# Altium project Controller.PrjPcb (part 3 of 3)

## Sheet Fault Logic - S.SchDoc: FAULT LOGIC (S) - 60KW GM4 DAB CONTROL
size 431 x 279 mm; Date: 02/2025; DocumentNumber: CRD60DD12N-GMB-CONTROL; Revision: 2.0; SheetNumber: 8; SheetTotal: 12; SheetSize: B
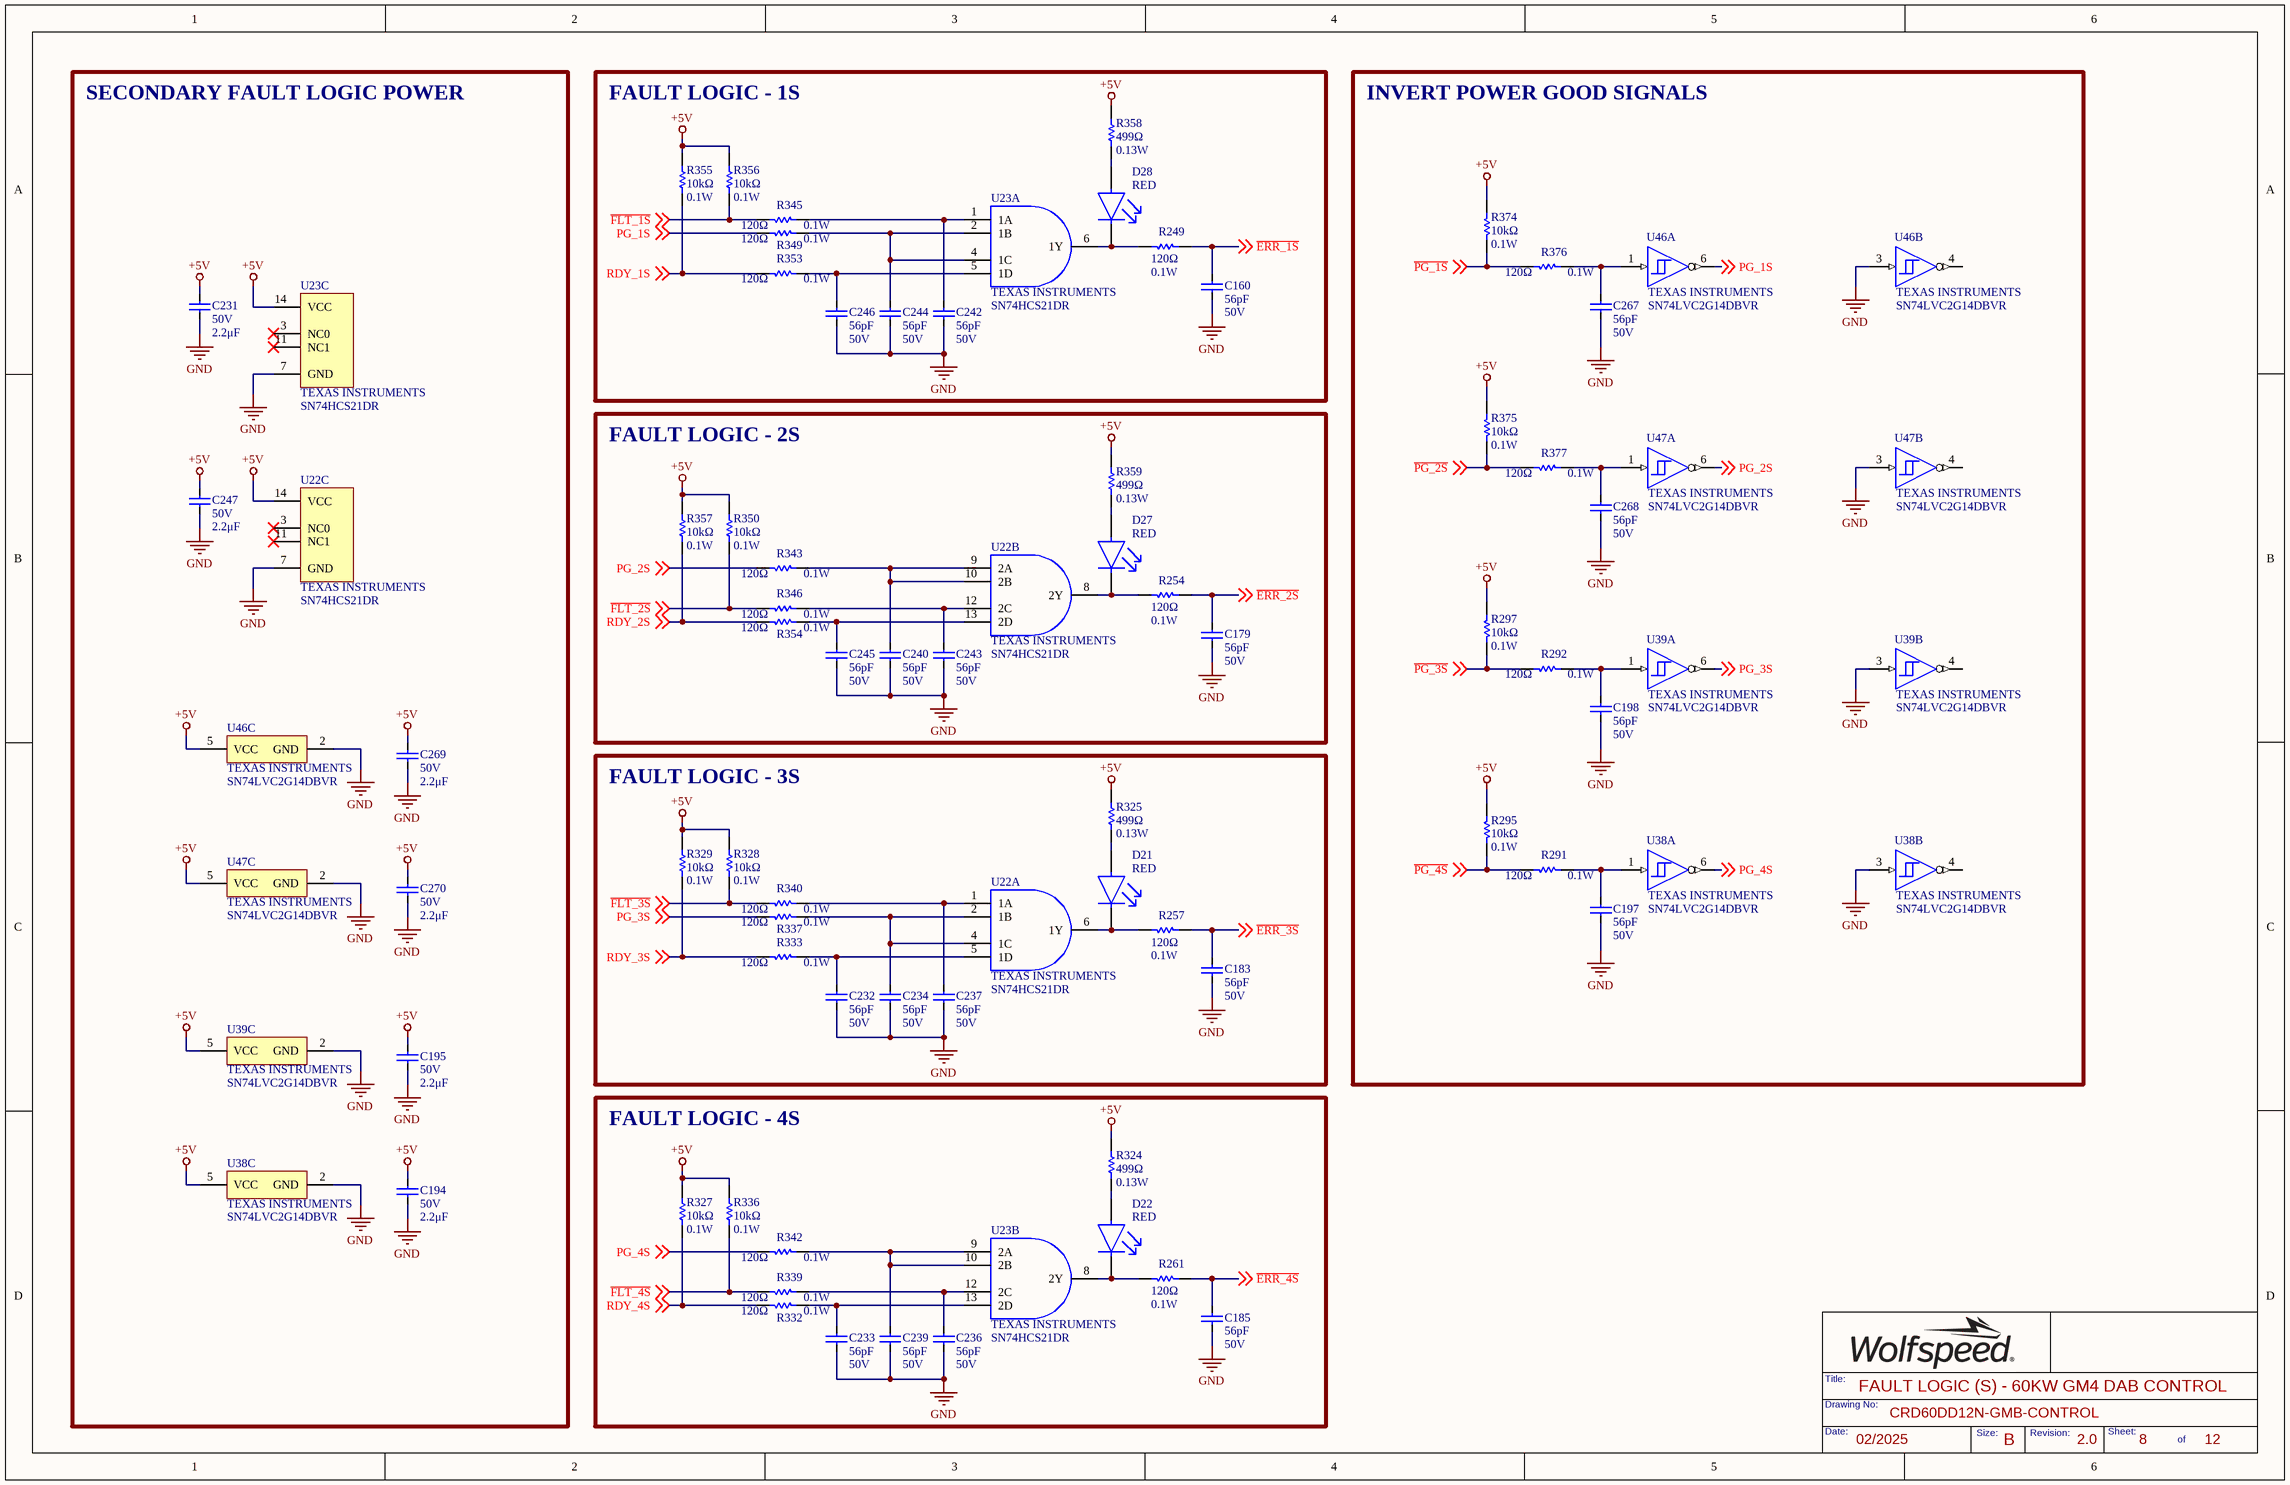
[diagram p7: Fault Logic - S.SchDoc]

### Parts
C160  Capacitance: 56pF  Voltage Rating: 50V  [FP-C0603C-CF-IPC_B]  (hidden comment: CL10C560JB8NNNC)
C179  Capacitance: 56pF  Voltage Rating: 50V  [FP-C0603C-CF-IPC_B]  (hidden comment: CL10C560JB8NNNC)
C183  Capacitance: 56pF  Voltage Rating: 50V  [FP-C0603C-CF-IPC_B]  (hidden comment: CL10C560JB8NNNC)
C185  Capacitance: 56pF  Voltage Rating: 50V  [FP-C0603C-CF-IPC_B]  (hidden comment: CL10C560JB8NNNC)
C194  Voltage Rating: 50V  Capacitance: 2.2μF  [FP-C0603C-CF-IPC_B]  (hidden comment: GRT188R61H225ME13D)
C195  Voltage Rating: 50V  Capacitance: 2.2μF  [FP-C0603C-CF-IPC_B]  (hidden comment: GRT188R61H225ME13D)
C197  Capacitance: 56pF  Voltage Rating: 50V  [FP-C0603C-CF-IPC_B]  (hidden comment: CL10C560JB8NNNC)
C198  Capacitance: 56pF  Voltage Rating: 50V  [FP-C0603C-CF-IPC_B]  (hidden comment: CL10C560JB8NNNC)
C231  Voltage Rating: 50V  Capacitance: 2.2μF  [FP-C0603C-CF-IPC_B]  (hidden comment: GRT188R61H225ME13D)
C232  Capacitance: 56pF  Voltage Rating: 50V  [FP-C0603C-CF-IPC_B]  (hidden comment: CL10C560JB8NNNC)
C233  Capacitance: 56pF  Voltage Rating: 50V  [FP-C0603C-CF-IPC_B]  (hidden comment: CL10C560JB8NNNC)
C234  Capacitance: 56pF  Voltage Rating: 50V  [FP-C0603C-CF-IPC_B]  (hidden comment: CL10C560JB8NNNC)
C236  Capacitance: 56pF  Voltage Rating: 50V  [FP-C0603C-CF-IPC_B]  (hidden comment: CL10C560JB8NNNC)
C237  Capacitance: 56pF  Voltage Rating: 50V  [FP-C0603C-CF-IPC_B]  (hidden comment: CL10C560JB8NNNC)
C239  Capacitance: 56pF  Voltage Rating: 50V  [FP-C0603C-CF-IPC_B]  (hidden comment: CL10C560JB8NNNC)
C240  Capacitance: 56pF  Voltage Rating: 50V  [FP-C0603C-CF-IPC_B]  (hidden comment: CL10C560JB8NNNC)
C242  Capacitance: 56pF  Voltage Rating: 50V  [FP-C0603C-CF-IPC_B]  (hidden comment: CL10C560JB8NNNC)
C243  Capacitance: 56pF  Voltage Rating: 50V  [FP-C0603C-CF-IPC_B]  (hidden comment: CL10C560JB8NNNC)
C244  Capacitance: 56pF  Voltage Rating: 50V  [FP-C0603C-CF-IPC_B]  (hidden comment: CL10C560JB8NNNC)
C245  Capacitance: 56pF  Voltage Rating: 50V  [FP-C0603C-CF-IPC_B]  (hidden comment: CL10C560JB8NNNC)
C246  Capacitance: 56pF  Voltage Rating: 50V  [FP-C0603C-CF-IPC_B]  (hidden comment: CL10C560JB8NNNC)
C247  Voltage Rating: 50V  Capacitance: 2.2μF  [FP-C0603C-CF-IPC_B]  (hidden comment: GRT188R61H225ME13D)
C267  Capacitance: 56pF  Voltage Rating: 50V  [FP-C0603C-CF-IPC_B]  (hidden comment: CL10C560JB8NNNC)
C268  Capacitance: 56pF  Voltage Rating: 50V  [FP-C0603C-CF-IPC_B]  (hidden comment: CL10C560JB8NNNC)
C269  Voltage Rating: 50V  Capacitance: 2.2μF  [FP-C0603C-CF-IPC_B]  (hidden comment: GRT188R61H225ME13D)
C270  Voltage Rating: 50V  Capacitance: 2.2μF  [FP-C0603C-CF-IPC_B]  (hidden comment: GRT188R61H225ME13D)
D21  value RED  [FP-LTST-C171GKT-MFG-RED]  (hidden comment: HSMC-C170)
D22  value RED  [FP-LTST-C171GKT-MFG-RED]  (hidden comment: HSMC-C170)
D27  value RED  [FP-LTST-C171GKT-MFG-RED]  (hidden comment: HSMC-C170)
D28  value RED  [FP-LTST-C171GKT-MFG-RED]  (hidden comment: HSMC-C170)
R249  value 120Ω  Max Power Dissipation: 0.1W  [FP-MCR03-IPC_B]  (hidden comment: RC0603JR-07120RL)
R254  value 120Ω  Max Power Dissipation: 0.1W  [FP-MCR03-IPC_B]  (hidden comment: RC0603JR-07120RL)
R257  value 120Ω  Max Power Dissipation: 0.1W  [FP-MCR03-IPC_B]  (hidden comment: RC0603JR-07120RL)
R261  value 120Ω  Max Power Dissipation: 0.1W  [FP-MCR03-IPC_B]  (hidden comment: RC0603JR-07120RL)
R291  value 120Ω  Max Power Dissipation: 0.1W  [FP-MCR03-IPC_B]  (hidden comment: RC0603JR-07120RL)
R292  value 120Ω  Max Power Dissipation: 0.1W  [FP-MCR03-IPC_B]  (hidden comment: RC0603JR-07120RL)
R295  value 10kΩ  Max Power Dissipation: 0.1W  [FP-MCR03-IPC_B]  (hidden comment: ERJ3EKF1002V)
R297  value 10kΩ  Max Power Dissipation: 0.1W  [FP-MCR03-IPC_B]  (hidden comment: ERJ3EKF1002V)
R324  Resistance: 499Ω  Max Power Dissipation: 0.13W  [FP-MCR10-IPC_A]  (hidden comment: RC0805FR-07499RL)
R325  Resistance: 499Ω  Max Power Dissipation: 0.13W  [FP-MCR10-IPC_A]  (hidden comment: RC0805FR-07499RL)
R327  value 10kΩ  Max Power Dissipation: 0.1W  [FP-MCR03-IPC_B]  (hidden comment: ERJ3EKF1002V)
R328  value 10kΩ  Max Power Dissipation: 0.1W  [FP-MCR03-IPC_B]  (hidden comment: ERJ3EKF1002V)
R329  value 10kΩ  Max Power Dissipation: 0.1W  [FP-MCR03-IPC_B]  (hidden comment: ERJ3EKF1002V)
R332  value 120Ω  Max Power Dissipation: 0.1W  [FP-MCR03-IPC_B]  (hidden comment: RC0603JR-07120RL)
R333  value 120Ω  Max Power Dissipation: 0.1W  [FP-MCR03-IPC_B]  (hidden comment: RC0603JR-07120RL)
R336  value 10kΩ  Max Power Dissipation: 0.1W  [FP-MCR03-IPC_B]  (hidden comment: ERJ3EKF1002V)
R337  value 120Ω  Max Power Dissipation: 0.1W  [FP-MCR03-IPC_B]  (hidden comment: RC0603JR-07120RL)
R339  value 120Ω  Max Power Dissipation: 0.1W  [FP-MCR03-IPC_B]  (hidden comment: RC0603JR-07120RL)
R340  value 120Ω  Max Power Dissipation: 0.1W  [FP-MCR03-IPC_B]  (hidden comment: RC0603JR-07120RL)
R342  value 120Ω  Max Power Dissipation: 0.1W  [FP-MCR03-IPC_B]  (hidden comment: RC0603JR-07120RL)
R343  value 120Ω  Max Power Dissipation: 0.1W  [FP-MCR03-IPC_B]  (hidden comment: RC0603JR-07120RL)
R345  value 120Ω  Max Power Dissipation: 0.1W  [FP-MCR03-IPC_B]  (hidden comment: RC0603JR-07120RL)
R346  value 120Ω  Max Power Dissipation: 0.1W  [FP-MCR03-IPC_B]  (hidden comment: RC0603JR-07120RL)
R349  value 120Ω  Max Power Dissipation: 0.1W  [FP-MCR03-IPC_B]  (hidden comment: RC0603JR-07120RL)
R350  value 10kΩ  Max Power Dissipation: 0.1W  [FP-MCR03-IPC_B]  (hidden comment: ERJ3EKF1002V)
R353  value 120Ω  Max Power Dissipation: 0.1W  [FP-MCR03-IPC_B]  (hidden comment: RC0603JR-07120RL)
R354  value 120Ω  Max Power Dissipation: 0.1W  [FP-MCR03-IPC_B]  (hidden comment: RC0603JR-07120RL)
R355  value 10kΩ  Max Power Dissipation: 0.1W  [FP-MCR03-IPC_B]  (hidden comment: ERJ3EKF1002V)
R356  value 10kΩ  Max Power Dissipation: 0.1W  [FP-MCR03-IPC_B]  (hidden comment: ERJ3EKF1002V)
R357  value 10kΩ  Max Power Dissipation: 0.1W  [FP-MCR03-IPC_B]  (hidden comment: ERJ3EKF1002V)
R358  Resistance: 499Ω  Max Power Dissipation: 0.13W  [FP-MCR10-IPC_A]  (hidden comment: RC0805FR-07499RL)
R359  Resistance: 499Ω  Max Power Dissipation: 0.13W  [FP-MCR10-IPC_A]  (hidden comment: RC0805FR-07499RL)
R374  value 10kΩ  Max Power Dissipation: 0.1W  [FP-MCR03-IPC_B]  (hidden comment: ERJ3EKF1002V)
R375  value 10kΩ  Max Power Dissipation: 0.1W  [FP-MCR03-IPC_B]  (hidden comment: ERJ3EKF1002V)
R376  value 120Ω  Max Power Dissipation: 0.1W  [FP-MCR03-IPC_B]  (hidden comment: RC0603JR-07120RL)
R377  value 120Ω  Max Power Dissipation: 0.1W  [FP-MCR03-IPC_B]  (hidden comment: RC0603JR-07120RL)
U22  Manufacturer: TEXAS INSTRUMENTS  [SOIC_S21DR_TEX]  (hidden comment: SN74HCS21DR)  (parts A,B,C of 3)
U23  Manufacturer: TEXAS INSTRUMENTS  [SOIC_S21DR_TEX]  (hidden comment: SN74HCS21DR)  (parts A,B,C of 3)
U38  Manufacturer: TEXAS INSTRUMENTS  [DBV0006A_M]  (hidden comment: SN74LVC2G14DBVR)  (parts A,B,C of 3)
U39  Manufacturer: TEXAS INSTRUMENTS  [DBV0006A_M]  (hidden comment: SN74LVC2G14DBVR)  (parts A,B,C of 3)
U46  Manufacturer: TEXAS INSTRUMENTS  [DBV0006A_M]  (hidden comment: SN74LVC2G14DBVR)  (parts A,B,C of 3)
U47  Manufacturer: TEXAS INSTRUMENTS  [DBV0006A_M]  (hidden comment: SN74LVC2G14DBVR)  (parts A,B,C of 3)

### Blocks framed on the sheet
SECONDARY FAULT LOGIC POWER: C194 C195 C231 C247 C269 C270 U22 U23 U38 U39 U46 U47
FAULT LOGIC - 1S: C160 C242 C244 C246 D28 R249 R345 R349 R353 R355 R356 R358 U23
INVERT POWER GOOD SIGNALS: C197 C198 C267 C268 R291 R292 R295 R297 R374-R377 U38 U39 U46 U47
FAULT LOGIC - 2S: C179 C240 C243 C245 D27 R254 R343 R346 R350 R354 R357 R359 U22
FAULT LOGIC - 3S: C183 C232 C234 C237 D21 R257 R325 R328 R329 R333 R337 R340 U22
FAULT LOGIC - 4S: C185 C233 C236 C239 D22 R261 R324 R327 R332 R336 R339 R342 U23

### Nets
+5V: C194.1 C195.1 C231.1 C247.1 C269.1 C270.1 R295.1 R297.1 R324.2 R325.2 R327.2 R328.2 R329.2 R336.2 R350.2 R355.2 R356.2 R357.2 R358.2 R359.2 R374.1 R375.1 U22.14(VCC) U23.14(VCC) U38.5(VCC) U39.5(VCC) U46.5(VCC) U47.5(VCC)
GND: C160.2 C179.2 C183.2 C185.2 C194.2 C195.2 C197.2 C198.2 C231.2 C232.2 C233.2 C234.2 C236.2 C237.2 C239.2 C240.2 C242.2 C243.2 C244.2 C245.2 C246.2 C247.2 C267.2 C268.2 C269.2 C270.2 U22.7(GND) U23.7(GND) U38.2(GND) U38.3(2A) U39.2(GND) U39.3(2A) U46.2(GND) U46.3(2A) U47.2(GND) U47.3(2A)
~{ERR_1S}: C160.1 R249.1 ; off-sheet ~{ERR_1S}
~{ERR_2S}: C179.1 R254.1 ; off-sheet ~{ERR_2S}
~{ERR_3S}: C183.1 R257.1 ; off-sheet ~{ERR_3S}
~{ERR_4S}: C185.1 R261.1 ; off-sheet ~{ERR_4S}
~{FLT_1S}: R345.2 R356.1 ; off-sheet ~{FLT_1S}
~{FLT_2S}: R346.2 R350.1 ; off-sheet ~{FLT_2S}
~{FLT_3S}: R328.1 R340.2 ; off-sheet ~{FLT_3S}
~{FLT_4S}: R336.1 R339.2 ; off-sheet ~{FLT_4S}
~{PG_1S}: R374.2 R376.2 ; off-sheet ~{PG_1S}
~{PG_2S}: R375.2 R377.2 ; off-sheet ~{PG_2S}
~{PG_3S}: R292.2 R297.2 ; off-sheet ~{PG_3S}
~{PG_4S}: R291.2 R295.2 ; off-sheet ~{PG_4S}
PG_1S: R349.2 U46.6(1Y) ; off-sheet PG_1S
PG_2S: R343.2 U47.6(1Y) ; off-sheet PG_2S
PG_3S: R337.2 U39.6(1Y) ; off-sheet PG_3S
PG_4S: R342.2 U38.6(1Y) ; off-sheet PG_4S
RDY_1S: R353.2 R355.1 ; off-sheet RDY_1S
RDY_2S: R354.2 R357.1 ; off-sheet RDY_2S
RDY_3S: R329.1 R333.2 ; off-sheet RDY_3S
RDY_4S: R327.1 R332.2 ; off-sheet RDY_4S
NetC197_1: C197.1 R291.1 U38.1(1A)
NetC198_1: C198.1 R292.1 U39.1(1A)
NetC232_1: C232.1 R333.1 U22.5(1D)
NetC233_1: C233.1 R332.1 U23.13(2D)
NetC234_1: C234.1 R337.1 U22.2(1B) U22.4(1C)
NetC236_1: C236.1 R339.1 U23.12(2C)
NetC237_1: C237.1 R340.1 U22.1(1A)
NetC239_1: C239.1 R342.1 U23.9(2A) U23.10(2B)
NetC240_1: C240.1 R343.1 U22.9(2A) U22.10(2B)
NetC242_1: C242.1 R345.1 U23.1(1A)
NetC243_1: C243.1 R346.1 U22.12(2C)
NetC244_1: C244.1 R349.1 U23.2(1B) U23.4(1C)
NetC245_1: C245.1 R354.1 U22.13(2D)
NetC246_1: C246.1 R353.1 U23.5(1D)
NetC267_1: C267.1 R376.1 U46.1(1A)
NetC268_1: C268.1 R377.1 U47.1(1A)
NetD21_1: D21.1(C) R257.2 U22.6(1Y)
NetD21_2: D21.2(A) R325.1
NetD22_1: D22.1(C) R261.2 U23.8(2Y)
NetD22_2: D22.2(A) R324.1
NetD27_1: D27.1(C) R254.2 U22.8(2Y)
NetD27_2: D27.2(A) R359.1
NetD28_1: D28.1(C) R249.2 U23.6(1Y)
NetD28_2: D28.2(A) R358.1

Not connected (* = marked no-connect by the designer): U22 3(NC0)* 11(NC1)*; U23 3(NC0)* 11(NC1)*; U38 4(2Y); U39 4(2Y); U46 4(2Y); U47 4(2Y)

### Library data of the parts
C160 C179 C183 C185 C197 C198 C232-C234 C236 C237 C239 C240 C242-C246 C267 C268 = CL10C560JB8NNNC: CAP CER 56PF 50V C0G/NP0 0603; Manufacturer: SAMSUNG; Material: Ceramic; Tolerance: 5%; Dielectric: C0G; Temperature Coefficient: 30ppm/°C
C194 C195 C231 C247 C269 C270 = GRT188R61H225ME13D: CAP CER 2.2UF 50V X5R 0603; Manufacturer: MURATA; Tolerance: 20%; Value: 2.2μF
D21 D22 D27 D28 = HSMC-C170: LED RED DIFFUSED CHIP SMD; Manufacturer: BROADCOM
R249 R254 R257 R261 R291 R292 R332 R333 R337 R339 R340 R342 R343 R345 R346 R349 R353 R354 R376 R377 = RC0603JR-07120RL: RES SMD 120 OHM 5% 1/10W 0603; Manufacturer: YAGEO; Voltage Rating (DC): 50V; Temperature Coefficient: 100ppm/°C; Power Rating: 100mW
R295 R297 R327-R329 R336 R350 R355-R357 R374 R375 = ERJ3EKF1002V: RES SMD 10K OHM 1% 1/10W 0603; Manufacturer: PANASONIC; Manufacturer Part Number: ERJ-3EKF1002V; Temperature Coefficient: 100ppm/°C; Power Rating: 100mW; Voltage Rating: 75V
R324 R325 R358 R359 = RC0805FR-07499RL: RES 499 OHM 1% 1/8W 0805; Manufacturer: YAGEO; Power Rating: 125mW; Voltage Rating: 150V; Temperature Coefficient: 100ppm/°C; Value: 499Ω
U22 U23 = SN74HCS21DR: IC GATE AND 2CH 4-INP 14SOIC
U38 U39 U46 U47 = CMP-0859-00232-4: IC INVERTER 2CH 2-INP SOT23-6; ICC @ Nom Voltage(Max)(mA): 0.01; Input Type: CMOS/TTL; Logic: Inverting; Output Drive (IOL/IOH)(Max)(mA): 32/-32; VCC(Min)(V): 1.65; VCC(Max)(V): 5.5; Rating: Catalog; Technology Family: LVC; Sub-Family: Inverting Buffer/Driver; 3-State Output: No; Schmitt Trigger: Yes; Output Type: CMOS; tpd @ Nom Voltage(Max)(ns): 9.5,5.7,5.4,4.3; Voltage(Nom)(V): 1.8,2.5,3.3,5; F @ Nom Voltage(Max)(Mhz): 150; Bits(#): 2

## Sheet Level Shifting.SchDoc: LEVEL SHIFT - 60KW GM4 DAB CONTROL
size 431 x 279 mm; Date: 02/2025; DocumentNumber: CRD60DD12N-GMB-CONTROL; Revision: 2.0; SheetNumber: 9; SheetTotal: 12; SheetSize: B
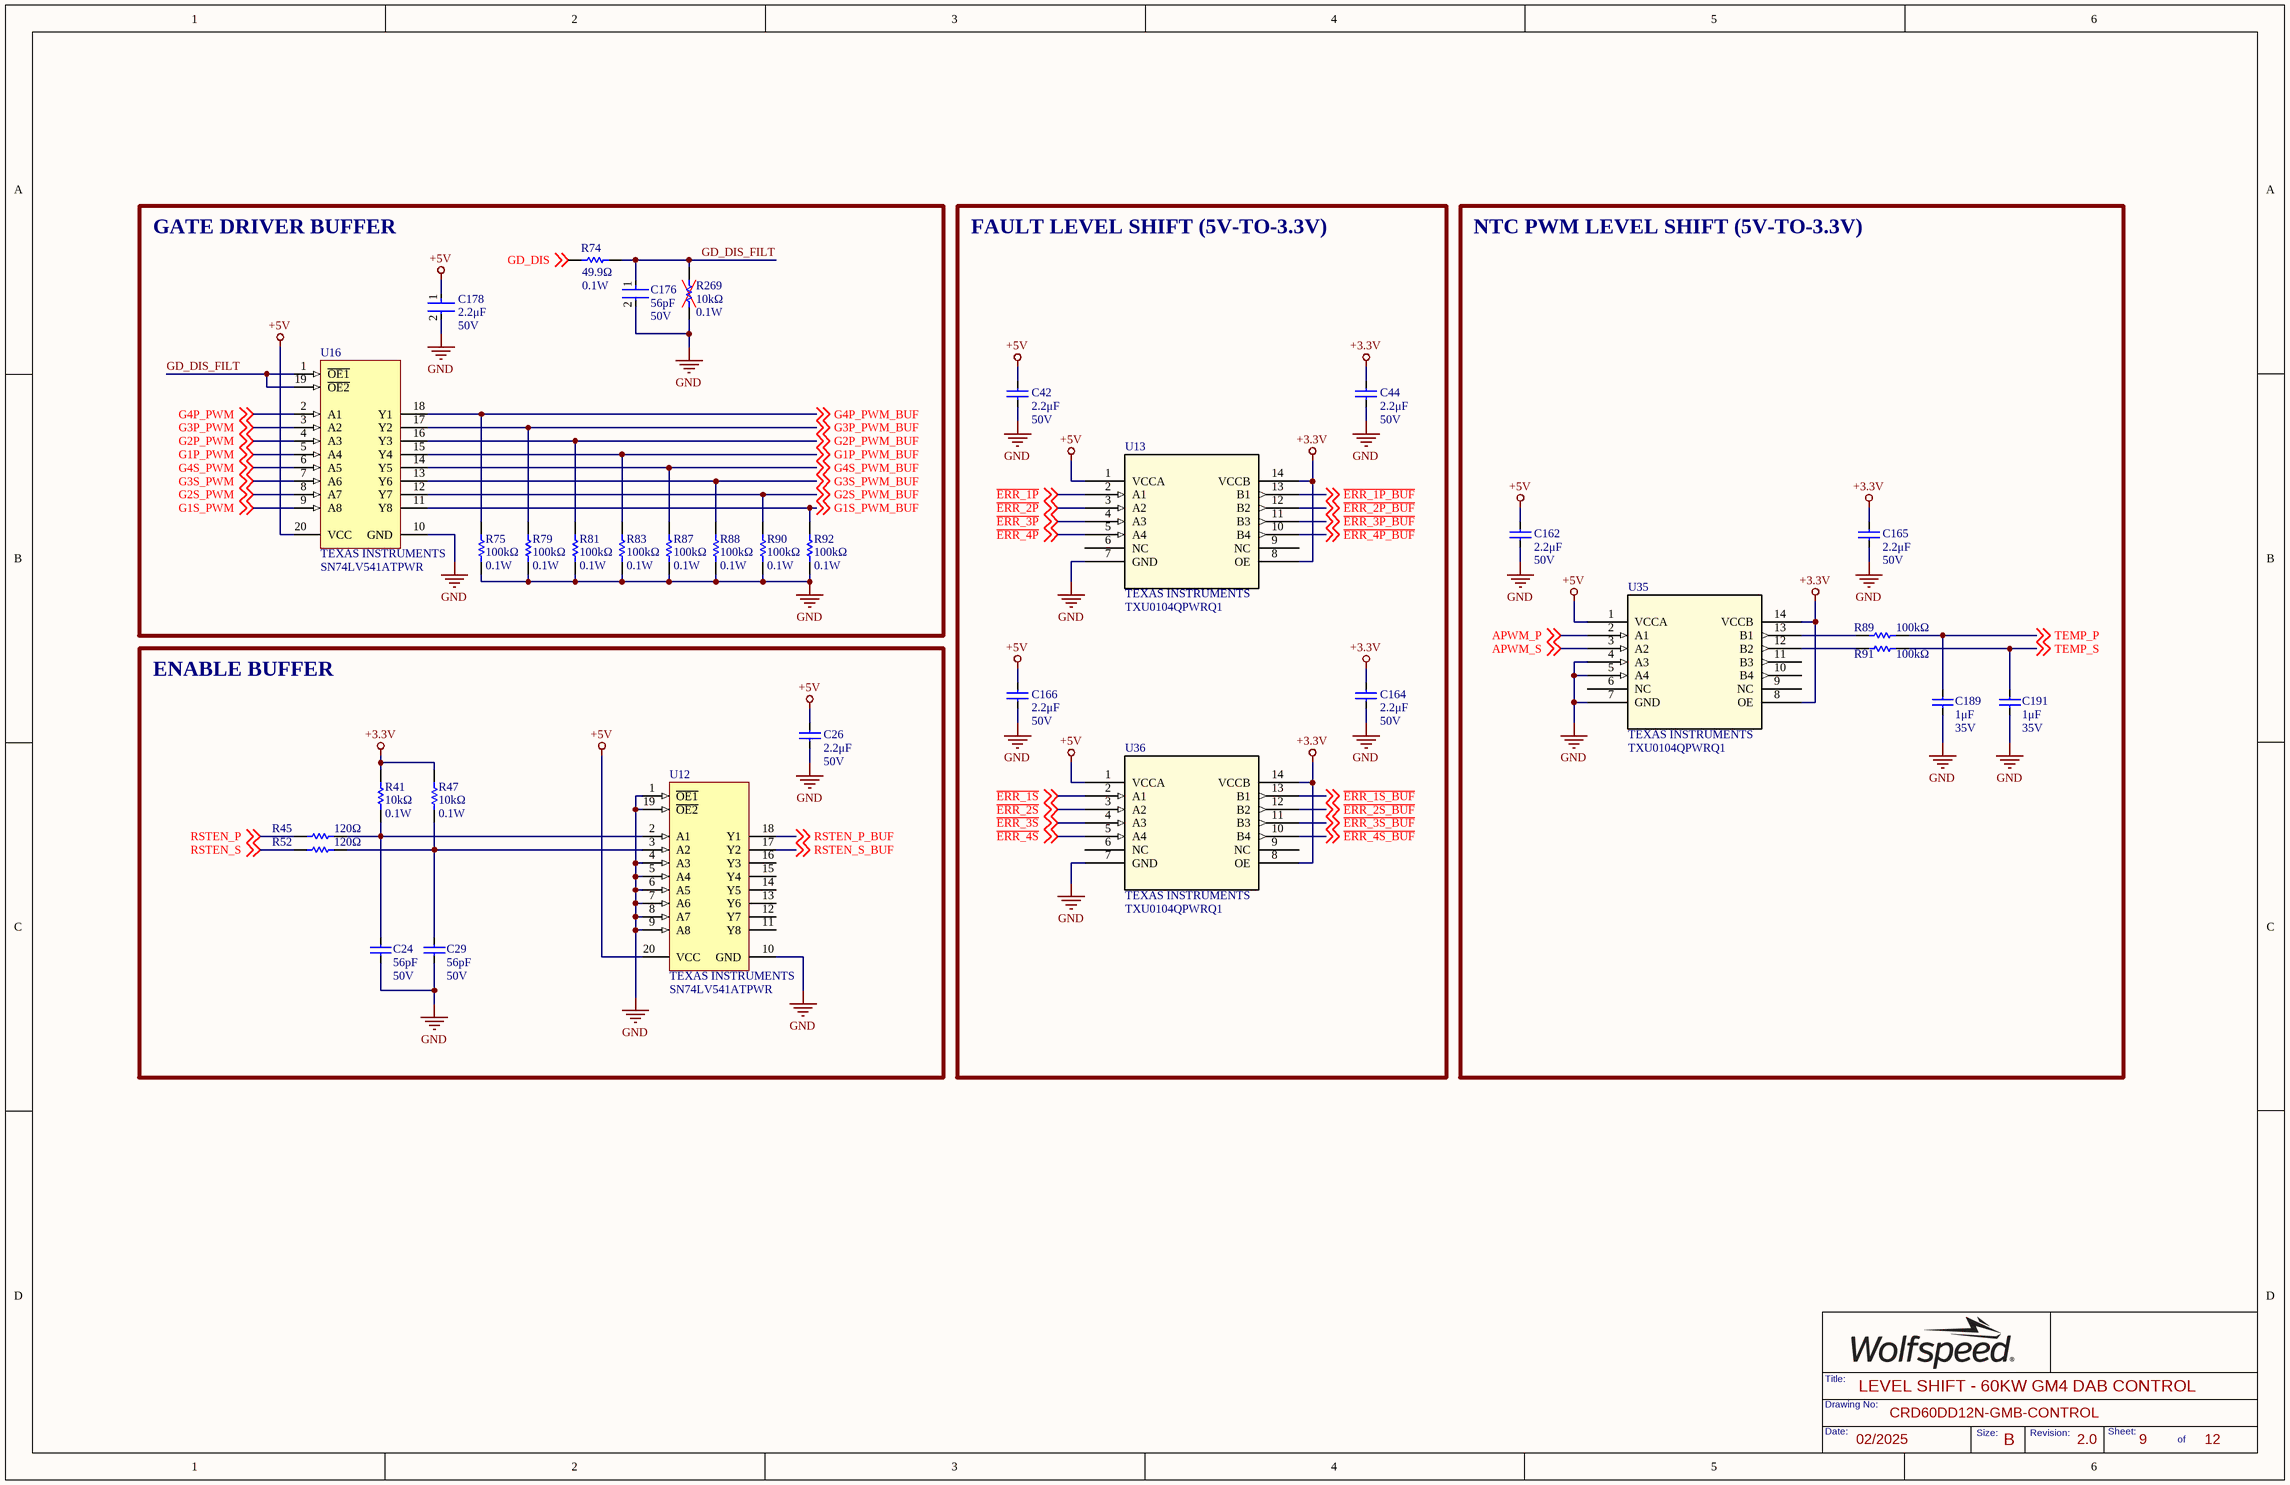
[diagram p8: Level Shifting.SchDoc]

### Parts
C24  Capacitance: 56pF  Voltage Rating: 50V  [FP-C0603C-CF-IPC_B]  (hidden comment: CL10C560JB8NNNC)
C26  Voltage Rating: 50V  Capacitance: 2.2μF  [FP-C0603C-CF-IPC_B]  (hidden comment: GRT188R61H225ME13D)
C29  Capacitance: 56pF  Voltage Rating: 50V  [FP-C0603C-CF-IPC_B]  (hidden comment: CL10C560JB8NNNC)
C42  Voltage Rating: 50V  Capacitance: 2.2μF  [FP-C0603C-CF-IPC_B]  (hidden comment: GRT188R61H225ME13D)
C44  Voltage Rating: 50V  Capacitance: 2.2μF  [FP-C0603C-CF-IPC_B]  (hidden comment: GRT188R61H225ME13D)
C162  Voltage Rating: 50V  Capacitance: 2.2μF  [FP-C0603C-CF-IPC_B]  (hidden comment: GRT188R61H225ME13D)
C164  Voltage Rating: 50V  Capacitance: 2.2μF  [FP-C0603C-CF-IPC_B]  (hidden comment: GRT188R61H225ME13D)
C165  Voltage Rating: 50V  Capacitance: 2.2μF  [FP-C0603C-CF-IPC_B]  (hidden comment: GRT188R61H225ME13D)
C166  Voltage Rating: 50V  Capacitance: 2.2μF  [FP-C0603C-CF-IPC_B]  (hidden comment: GRT188R61H225ME13D)
C176  Capacitance: 56pF  Voltage Rating: 50V  [FP-C0603C-CF-IPC_B]  (hidden comment: CL10C560JB8NNNC)
C178  Voltage Rating: 50V  Capacitance: 2.2μF  [FP-C0603C-CF-IPC_B]  (hidden comment: GRT188R61H225ME13D)
C189  value 1μF  Voltage Rating: 35V  [FP-C0603C-CF-IPC_B]  (hidden comment: CGA3E1X7R1V105K080AC)
C191  value 1μF  Voltage Rating: 35V  [FP-C0603C-CF-IPC_B]  (hidden comment: CGA3E1X7R1V105K080AC)
R41  Resistance: 10kΩ  Max Power Dissipation: 0.1W  [FP-MCR03-IPC_B]  (hidden comment: ERJ3EKF1002V)
R45  value 120Ω  [FP-MCR03-IPC_B]  (hidden comment: RC0603JR-07120RL)
R47  Resistance: 10kΩ  Max Power Dissipation: 0.1W  [FP-MCR03-IPC_B]  (hidden comment: ERJ3EKF1002V)
R52  value 120Ω  [FP-MCR03-IPC_B]  (hidden comment: RC0603JR-07120RL)
R74  Resistance: 49.9Ω  Power Rating: 0.1W  [FP-MCR03-IPC_B]  (hidden comment: ERJ-3EKF49R9V)
R75  Resistance: 100kΩ  Power Rating: 0.1W  [FP-MCR03-IPC_B]  (hidden comment: RC0603FR-07100KL)
R79  Resistance: 100kΩ  Power Rating: 0.1W  [FP-MCR03-IPC_B]  (hidden comment: RC0603FR-07100KL)
R81  Resistance: 100kΩ  Power Rating: 0.1W  [FP-MCR03-IPC_B]  (hidden comment: RC0603FR-07100KL)
R83  Resistance: 100kΩ  Power Rating: 0.1W  [FP-MCR03-IPC_B]  (hidden comment: RC0603FR-07100KL)
R87  Resistance: 100kΩ  Power Rating: 0.1W  [FP-MCR03-IPC_B]  (hidden comment: RC0603FR-07100KL)
R88  Resistance: 100kΩ  Power Rating: 0.1W  [FP-MCR03-IPC_B]  (hidden comment: RC0603FR-07100KL)
R89  Resistance: 100kΩ  [FP-MCR03-IPC_B]  (hidden comment: RC0603FR-07100KL)
R90  Resistance: 100kΩ  Power Rating: 0.1W  [FP-MCR03-IPC_B]  (hidden comment: RC0603FR-07100KL)
R91  Resistance: 100kΩ  [FP-MCR03-IPC_B]  (hidden comment: RC0603FR-07100KL)
R92  Resistance: 100kΩ  Power Rating: 0.1W  [FP-MCR03-IPC_B]  (hidden comment: RC0603FR-07100KL)
R269  Resistance: 10kΩ  Max Power Dissipation: 0.1W  [FP-MCR03-IPC_B]  (hidden comment: ERJ3EKF1002V)
U12  Manufacturer: TEXAS INSTRUMENTS  [PW0020A_L]  (hidden comment: SN74LV541ATPWR)
U13  TXU0104QPWRQ1  Manufacturer: TEXAS INSTRUMENTS  [SOIC_QPWRQ1_TEX]
U16  Manufacturer: TEXAS INSTRUMENTS  [PW0020A_L]  (hidden comment: SN74LV541ATPWR)
U35  TXU0104QPWRQ1  Manufacturer: TEXAS INSTRUMENTS  [SOIC_QPWRQ1_TEX]
U36  TXU0104QPWRQ1  Manufacturer: TEXAS INSTRUMENTS  [SOIC_QPWRQ1_TEX]

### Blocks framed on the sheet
GATE DRIVER BUFFER: C176 C178 R74 R75 R79 R81 R83 R87 R88 R90 R92 R269 U16
FAULT LEVEL SHIFT (5V-TO-3.3V): C42 C44 C164 C166 U13 U36
NTC PWM LEVEL SHIFT (5V-TO-3.3V): C162 C165 C189 C191 R89 R91 U35
ENABLE BUFFER: C24 C26 C29 R41 R45 R47 R52 U12

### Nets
+3.3V: C44.1 C164.1 C165.1 R41.2 R47.2 U13.8(OE) U13.14(VCCB) U35.8(OE) U35.14(VCCB) U36.8(OE) U36.14(VCCB)
+5V: C26.1 C42.1 C162.1 C166.1 C178.1 U12.20(VCC) U13.1(VCCA) U16.20(VCC) U35.1(VCCA) U36.1(VCCA)
GND: C24.2 C26.2 C29.2 C42.2 C44.2 C162.2 C164.2 C165.2 C166.2 C176.2 C178.2 C189.2 C191.2 R75.1 R79.1 R81.1 R83.1 R87.1 R88.1 R90.1 R92.1 R269.1 U12.1(~{OE1}) U12.4(A3) U12.5(A4) U12.6(A5) U12.7(A6) U12.8(A7) U12.9(A8) U12.10(GND) U12.19(~{OE2}) U13.7(GND) U16.10(GND) U35.4(A3) U35.5(A4) U35.7(GND) U36.7(GND)
APWM_P: U35.2(A1) ; off-sheet APWM_P
APWM_S: U35.3(A2) ; off-sheet APWM_S
~{ERR_1P}: U13.2(A1) ; off-sheet ~{ERR_1P}
~{ERR_1P_BUF}: U13.13(B1) ; off-sheet ~{ERR_1P_BUF}
~{ERR_1S}: U36.2(A1) ; off-sheet ~{ERR_1S}
~{ERR_1S_BUF}: U36.13(B1) ; off-sheet ~{ERR_1S_BUF}
~{ERR_2P}: U13.3(A2) ; off-sheet ~{ERR_2P}
~{ERR_2P_BUF}: U13.12(B2) ; off-sheet ~{ERR_2P_BUF}
~{ERR_2S}: U36.3(A2) ; off-sheet ~{ERR_2S}
~{ERR_2S_BUF}: U36.12(B2) ; off-sheet ~{ERR_2S_BUF}
~{ERR_3P}: U13.4(A3) ; off-sheet ~{ERR_3P}
~{ERR_3P_BUF}: U13.11(B3) ; off-sheet ~{ERR_3P_BUF}
~{ERR_3S}: U36.4(A3) ; off-sheet ~{ERR_3S}
~{ERR_3S_BUF}: U36.11(B3) ; off-sheet ~{ERR_3S_BUF}
~{ERR_4P}: U13.5(A4) ; off-sheet ~{ERR_4P}
~{ERR_4P_BUF}: U13.10(B4) ; off-sheet ~{ERR_4P_BUF}
~{ERR_4S}: U36.5(A4) ; off-sheet ~{ERR_4S}
~{ERR_4S_BUF}: U36.10(B4) ; off-sheet ~{ERR_4S_BUF}
G1P_PWM: U16.5(A4) ; off-sheet G1P_PWM
G1P_PWM_BUF: R83.2 U16.15(Y4) ; off-sheet G1P_PWM_BUF
G1S_PWM: U16.9(A8) ; off-sheet G1S_PWM
G1S_PWM_BUF: R92.2 U16.11(Y8) ; off-sheet G1S_PWM_BUF
G2P_PWM: U16.4(A3) ; off-sheet G2P_PWM
G2P_PWM_BUF: R81.2 U16.16(Y3) ; off-sheet G2P_PWM_BUF
G2S_PWM: U16.8(A7) ; off-sheet G2S_PWM
G2S_PWM_BUF: R90.2 U16.12(Y7) ; off-sheet G2S_PWM_BUF
G3P_PWM: U16.3(A2) ; off-sheet G3P_PWM
G3P_PWM_BUF: R79.2 U16.17(Y2) ; off-sheet G3P_PWM_BUF
G3S_PWM: U16.7(A6) ; off-sheet G3S_PWM
G3S_PWM_BUF: R88.2 U16.13(Y6) ; off-sheet G3S_PWM_BUF
G4P_PWM: U16.2(A1) ; off-sheet G4P_PWM
G4P_PWM_BUF: R75.2 U16.18(Y1) ; off-sheet G4P_PWM_BUF
G4S_PWM: U16.6(A5) ; off-sheet G4S_PWM
G4S_PWM_BUF: R87.2 U16.14(Y5) ; off-sheet G4S_PWM_BUF
GD_DIS: R74.1 ; off-sheet GD_DIS
GD_DIS_FILT: C176.1 R74.2 R269.2 U16.1(~{OE1}) U16.19(~{OE2})
RSTEN_P: R45.1 ; off-sheet RSTEN_P
RSTEN_P_BUF: U12.18(Y1) ; off-sheet RSTEN_P_BUF
RSTEN_S: R52.1 ; off-sheet RSTEN_S
RSTEN_S_BUF: U12.17(Y2) ; off-sheet RSTEN_S_BUF
TEMP_P: C189.1 R89.1 ; off-sheet TEMP_P
TEMP_S: C191.1 R91.1 ; off-sheet TEMP_S
NetC24_1: C24.1 R41.1 R45.2 U12.2(A1)
NetC29_1: C29.1 R47.1 R52.2 U12.3(A2)
NetR89_2: R89.2 U35.13(B1)
NetR91_2: R91.2 U35.12(B2)

Not connected (* = marked no-connect by the designer): U12 11(Y8) 12(Y7) 13(Y6) 14(Y5) 15(Y4) 16(Y3); U13 6(NC) 9(NC); U35 6(NC) 9(NC) 10(B4) 11(B3); U36 6(NC) 9(NC)

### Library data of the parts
C24 C29 C176 = CL10C560JB8NNNC: as C160 on sheet Fault Logic - S
C26 C42 C44 C162 C164-C166 C178 = GRT188R61H225ME13D: as C194 on sheet Fault Logic - S
C189 C191 = CGA3E1X7R1V105K080AC: CAP CER 1UF 35V X7R 0603; Manufacturer: TDK; Material: 4241ConductorMaterial; Tolerance: 10%
R41 R47 R269 = ERJ3EKF1002V: RES SMD 10K OHM 1% 1/10W 0603; Manufacturer: PANASONIC; Manufacturer Part Number: ERJ-3EKF1002V; Temperature Coefficient: 100ppm/°C; Power Rating: 100mW; Voltage Rating: 75V; Value: 10kΩ
R45 R52 = RC0603JR-07120RL: as R249 on sheet Fault Logic - S
R74 = ERJ-3EKF49R9V: RES SMD 49.9 OHM 1% 1/10W 0603; Manufacturer: PANASONIC; Temperature Coefficient: 100ppm/°C; Voltage Rating: 75V; Max Power Dissipation: 100mW; Voltage Rating (DC): 50V; Working Voltage: 6V; Value: 49.9Ω
R75 R79 R81 R83 R87-R92 = RC0603FR-07100KL: RES 100K OHM 1% 1/10W 0603; Manufacturer: YAGEO; Temperature Coefficient: 100ppm/°C; Voltage Rating: 50V; Working Voltage: 75V; Max Power Dissipation: 100mW; Value: 100kΩ
U12 U16 = CMP-0440-01163-3: IC BUF NON-INVERT 5.5V 20TSSOP; Bits(#): 8; Voltage(Nom)(V): 5; ICC @ Nom Voltage(Max)(mA): 0.02; VCC(Max)(V): 5.5; Output Type: CMOS; Rating: Catalog; Input Type: TTL; VCC(Min)(V): 4.5; F @ Nom Voltage(Max)(Mhz): 110; tpd @ Nom Voltage(Max)(ns): 7.9
U13 U35 U36 = TXU0104QPWRQ1: IC TRANSLATOR UNIDIR 14TSSOP

## Sheet Voltage Sense.SchDoc: VOLTAGE SENSE - 60KW GM4 DAB CONTROL
size 431 x 279 mm; Date: 02/2025; DocumentNumber: CRD60DD12N-GMB-CONTROL; Revision: 2.0; SheetNumber: 10; SheetTotal: 12; SheetSize: B
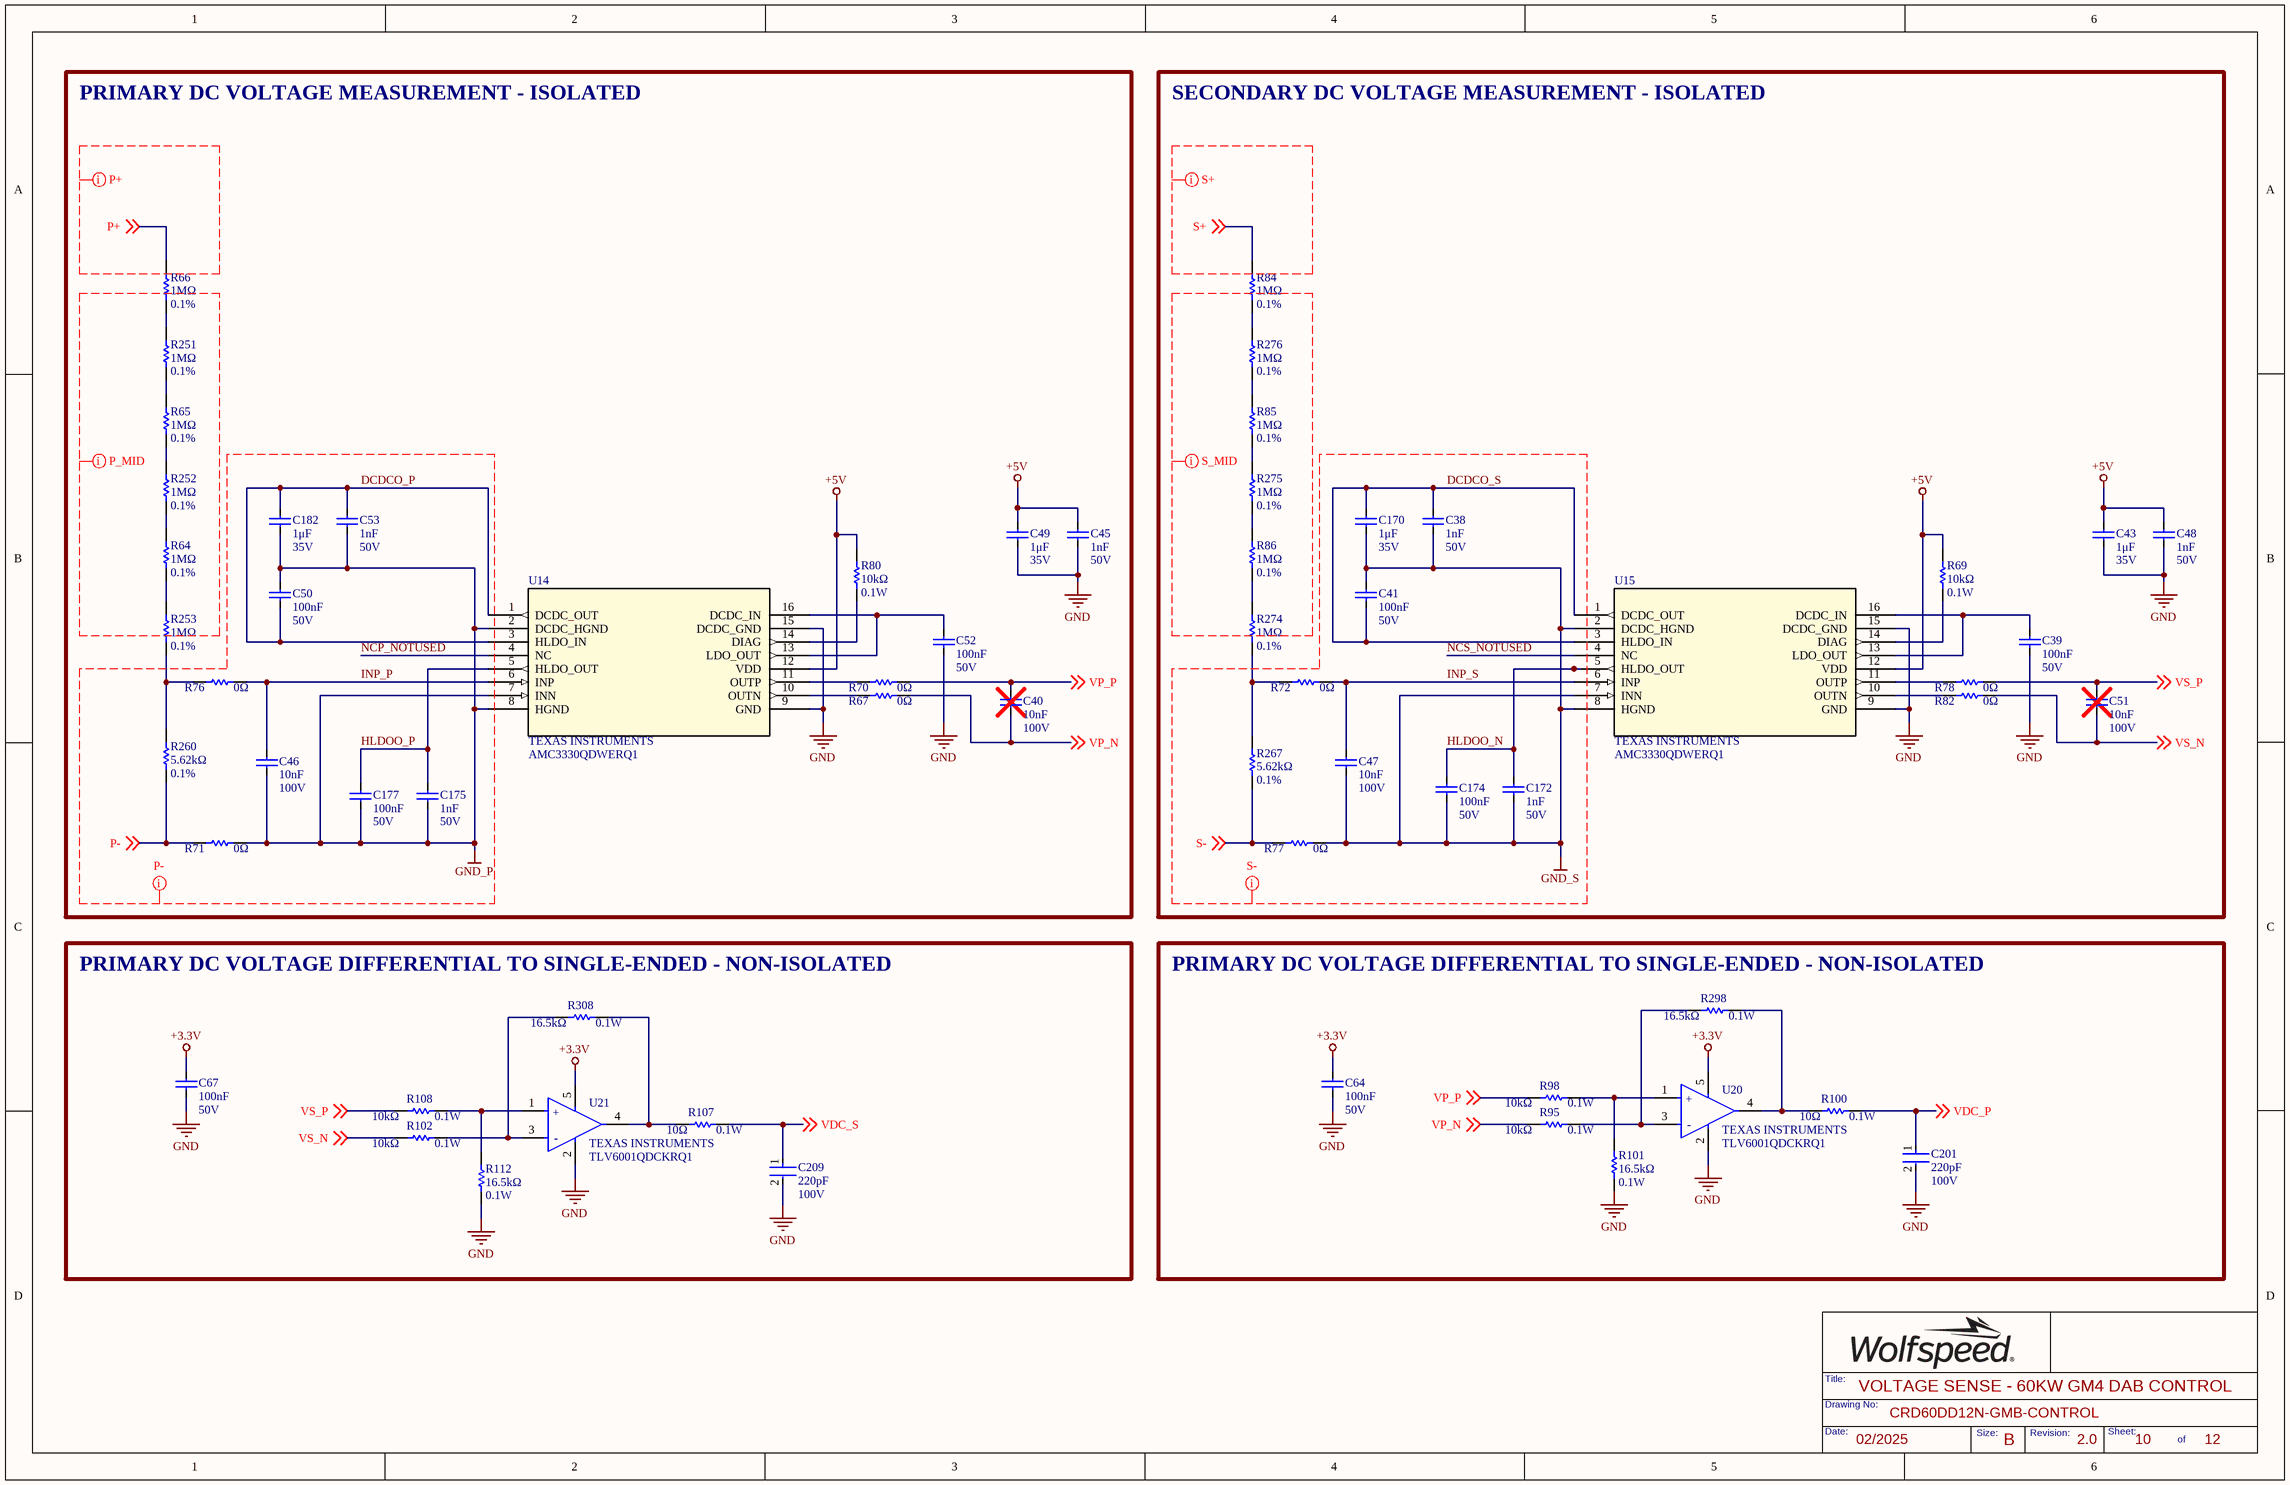
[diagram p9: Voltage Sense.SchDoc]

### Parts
C38  value 1nF  Voltage Rating: 50V  [FP-C0603C-CF-IPC_B]  (hidden comment: GCM188R71H102KA37D)
C39  value 100nF  Voltage: 50V  [FP-C0603C-CF-IPC_B]  (hidden comment: CGA3E2X7R1H104K080AA)
C40  value 10nF  Voltage: 100V  [FP-C0603C-CF-IPC_B]  (hidden comment: GRM188R72A103KA01D)
C41  value 100nF  Voltage: 50V  [FP-C0603C-CF-IPC_B]  (hidden comment: CGA3E2X7R1H104K080AA)
C43  value 1μF  Voltage Rating: 35V  [FP-C0603C-CF-IPC_B]  (hidden comment: CGA3E1X7R1V105K080AC)
C45  value 1nF  Voltage Rating: 50V  [FP-C0603C-CF-IPC_B]  (hidden comment: GCM188R71H102KA37D)
C46  value 10nF  Voltage: 100V  [FP-C0603C-CF-IPC_B]  (hidden comment: GRM188R72A103KA01D)
C47  value 10nF  Voltage: 100V  [FP-C0603C-CF-IPC_B]  (hidden comment: GRM188R72A103KA01D)
C48  value 1nF  Voltage Rating: 50V  [FP-C0603C-CF-IPC_B]  (hidden comment: GCM188R71H102KA37D)
C49  value 1μF  Voltage Rating: 35V  [FP-C0603C-CF-IPC_B]  (hidden comment: CGA3E1X7R1V105K080AC)
C50  value 100nF  Voltage: 50V  [FP-C0603C-CF-IPC_B]  (hidden comment: CGA3E2X7R1H104K080AA)
C51  value 10nF  Voltage: 100V  [FP-C0603C-CF-IPC_B]  (hidden comment: GRM188R72A103KA01D)
C52  value 100nF  Voltage: 50V  [FP-C0603C-CF-IPC_B]  (hidden comment: CGA3E2X7R1H104K080AA)
C53  value 1nF  Voltage Rating: 50V  [FP-C0603C-CF-IPC_B]  (hidden comment: GCM188R71H102KA37D)
C64  value 100nF  Voltage: 50V  [FP-C0603C-CF-IPC_B]  (hidden comment: CGA3E2X7R1H104K080AA)
C67  value 100nF  Voltage: 50V  [FP-C0603C-CF-IPC_B]  (hidden comment: CGA3E2X7R1H104K080AA)
C170  value 1μF  Voltage Rating: 35V  [FP-C0603C-CF-IPC_B]  (hidden comment: CGA3E1X7R1V105K080AC)
C172  value 1nF  Voltage Rating: 50V  [FP-C0603C-CF-IPC_B]  (hidden comment: GCM188R71H102KA37D)
C174  value 100nF  Voltage: 50V  [FP-C0603C-CF-IPC_B]  (hidden comment: CGA3E2X7R1H104K080AA)
C175  value 1nF  Voltage Rating: 50V  [FP-C0603C-CF-IPC_B]  (hidden comment: GCM188R71H102KA37D)
C177  value 100nF  Voltage: 50V  [FP-C0603C-CF-IPC_B]  (hidden comment: CGA3E2X7R1H104K080AA)
C182  value 1μF  Voltage Rating: 35V  [FP-C0603C-CF-IPC_B]  (hidden comment: CGA3E1X7R1V105K080AC)
C201  value 220pF  Voltage Rating: 100V  [FP-C0603C-CF-IPC_B]  (hidden comment: GCM1885C2A221JA16D)
C209  value 220pF  Voltage Rating: 100V  [FP-C0603C-CF-IPC_B]  (hidden comment: GCM1885C2A221JA16D)
R64  value 1MΩ  Tolerance: 0.1%  [RESC3116X65X40LL10T20]  (hidden comment: RNCF1206BKE1M00)
R65  value 1MΩ  Tolerance: 0.1%  [RESC3116X65X40LL10T20]  (hidden comment: RNCF1206BKE1M00)
R66  value 1MΩ  Tolerance: 0.1%  [RESC3116X65X40LL10T20]  (hidden comment: RNCF1206BKE1M00)
R67  Resistance: 0Ω  [FP-MCR03-IPC_B]  (hidden comment: CRCW06030000Z0EB)
R69  value 10kΩ  Max Power Dissipation: 0.1W  [FP-MCR03-IPC_B]  (hidden comment: ERJ3EKF1002V)
R70  Resistance: 0Ω  [FP-MCR03-IPC_B]  (hidden comment: CRCW06030000Z0EB)
R71  Resistance: 0Ω  [FP-MCR03-IPC_B]  (hidden comment: CRCW06030000Z0EB)
R72  Resistance: 0Ω  [FP-MCR03-IPC_B]  (hidden comment: CRCW06030000Z0EB)
R76  Resistance: 0Ω  [FP-MCR03-IPC_B]  (hidden comment: CRCW06030000Z0EB)
R77  Resistance: 0Ω  [FP-MCR03-IPC_B]  (hidden comment: CRCW06030000Z0EB)
R78  Resistance: 0Ω  [FP-MCR03-IPC_B]  (hidden comment: CRCW06030000Z0EB)
R80  value 10kΩ  Max Power Dissipation: 0.1W  [FP-MCR03-IPC_B]  (hidden comment: ERJ3EKF1002V)
R82  Resistance: 0Ω  [FP-MCR03-IPC_B]  (hidden comment: CRCW06030000Z0EB)
R84  value 1MΩ  Tolerance: 0.1%  [RESC3116X65X40LL10T20]  (hidden comment: RNCF1206BKE1M00)
R85  value 1MΩ  Tolerance: 0.1%  [RESC3116X65X40LL10T20]  (hidden comment: RNCF1206BKE1M00)
R86  value 1MΩ  Tolerance: 0.1%  [RESC3116X65X40LL10T20]  (hidden comment: RNCF1206BKE1M00)
R95  value 10kΩ  Max Power Dissipation: 0.1W  [FP-MCR03-IPC_B]  (hidden comment: ERJ3EKF1002V)
R98  value 10kΩ  Max Power Dissipation: 0.1W  [FP-MCR03-IPC_B]  (hidden comment: ERJ3EKF1002V)
R100  value 10Ω  Power: 0.1W  [FP-MCR03-IPC_B]  (hidden comment: RC0603JR-1310RL)
R101  value 16.5kΩ  Power Rating: 0.1W  [FP-MCR03-IPC_B]  (hidden comment: RT0603DRD0716K5L)
R102  value 10kΩ  Max Power Dissipation: 0.1W  [FP-MCR03-IPC_B]  (hidden comment: ERJ3EKF1002V)
R107  value 10Ω  Power: 0.1W  [FP-MCR03-IPC_B]  (hidden comment: RC0603JR-1310RL)
R108  value 10kΩ  Max Power Dissipation: 0.1W  [FP-MCR03-IPC_B]  (hidden comment: ERJ3EKF1002V)
R112  value 16.5kΩ  Power Rating: 0.1W  [FP-MCR03-IPC_B]  (hidden comment: RT0603DRD0716K5L)
R251  value 1MΩ  Tolerance: 0.1%  [RESC3116X65X40LL10T20]  (hidden comment: RNCF1206BKE1M00)
R252  value 1MΩ  Tolerance: 0.1%  [RESC3116X65X40LL10T20]  (hidden comment: RNCF1206BKE1M00)
R253  value 1MΩ  Tolerance: 0.1%  [RESC3116X65X40LL10T20]  (hidden comment: RNCF1206BKE1M00)
R260  value 5.62kΩ  Tolerance: 0.1%  [FP-MCR03-IPC_B]  (hidden comment: ERA-3AEB5621V)
R267  value 5.62kΩ  Tolerance: 0.1%  [FP-MCR03-IPC_B]  (hidden comment: ERA-3AEB5621V)
R274  value 1MΩ  Tolerance: 0.1%  [RESC3116X65X40LL10T20]  (hidden comment: RNCF1206BKE1M00)
R275  value 1MΩ  Tolerance: 0.1%  [RESC3116X65X40LL10T20]  (hidden comment: RNCF1206BKE1M00)
R276  value 1MΩ  Tolerance: 0.1%  [RESC3116X65X40LL10T20]  (hidden comment: RNCF1206BKE1M00)
R298  value 16.5kΩ  Power Rating: 0.1W  [FP-MCR03-IPC_B]  (hidden comment: RT0603DRD0716K5L)
R308  value 16.5kΩ  Power Rating: 0.1W  [FP-MCR03-IPC_B]  (hidden comment: RT0603DRD0716K5L)
U14  Manufacturer: TEXAS INSTRUMENTS  [SOIC16_DWE_TEX]  (hidden comment: AMC3330QDWERQ1)
U15  Manufacturer: TEXAS INSTRUMENTS  [SOIC16_DWE_TEX]  (hidden comment: AMC3330QDWERQ1)
U20  TLV6001QDCKRQ1  Manufacturer: TEXAS INSTRUMENTS  [FP-DCK0005A-IPC_B]
U21  TLV6001QDCKRQ1  Manufacturer: TEXAS INSTRUMENTS  [FP-DCK0005A-IPC_B]

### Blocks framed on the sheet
PRIMARY DC VOLTAGE MEASUREMENT - ISOLATED: C40 C45 C46 C49 C50 C52 C53 C175 C177 C182 R64-R67 R70 R71 R76 R80 R251-R253 R260 U14
SECONDARY DC VOLTAGE MEASUREMENT - ISOLATED: C38 C39 C41 C43 C47 C48 C51 C170 C172 C174 R69 R72 R77 R78 R82 R84-R86 R267 R274-R276 U15

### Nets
+3.3V: C64.1 C67.1 U20.5(V+) U21.5(V+)
+5V: C43.1 C45.1 C48.1 C49.1 R69.2 R80.2 U14.12(VDD) U15.12(VDD)
GND: C39.2 C43.2 C45.2 C48.2 C49.2 C52.2 C64.2 C67.2 C201.2 C209.2 R101.1 R112.1 U14.9(GND) U14.15(DCDC_GND) U15.9(GND) U15.15(DCDC_GND) U20.2(V-) U21.2(V-)
GND_P: C46.2 C50.1 C53.2 C175.2 C177.2 C182.2 R71.2 U14.2(DCDC_HGND) U14.7(INN) U14.8(HGND)
GND_S: C38.2 C41.1 C47.2 C170.2 C172.2 C174.2 R77.2 U15.2(DCDC_HGND) U15.7(INN) U15.8(HGND)
DCDCO_P: C50.2 C53.1 C182.1 U14.1(DCDC_OUT) U14.3(HLDO_IN)
DCDCO_S: C38.1 C41.2 C170.1 U15.1(DCDC_OUT) U15.3(HLDO_IN)
HLDOO_N: C172.1 C174.1 U15.5(HLDO_OUT)
HLDOO_P: C175.1 C177.1 U14.5(HLDO_OUT)
INP_P: C46.1 R76.2 U14.6(INP)
INP_S: C47.1 R72.2 U15.6(INP)
NCP_NOTUSED: U14.4(NC)
NCS_NOTUSED: U15.4(NC)
P+: R66.2 ; off-sheet P+
P-: R71.1 R260.1 ; off-sheet P-
S+: R84.2 ; off-sheet S+
S-: R77.1 R267.1 ; off-sheet S-
VDC_P: C201.1 R100.2 ; off-sheet VDC_P
VDC_S: C209.1 R107.2 ; off-sheet VDC_S
VP_N: C40.2 R67.2 R95.2 ; off-sheet VP_N
VP_P: C40.1 R70.2 R98.2 ; off-sheet VP_P
VS_N: C51.2 R82.2 R102.2 ; off-sheet VS_N
VS_P: C51.1 R78.2 R108.2 ; off-sheet VS_P
NetC39_1: C39.1 U15.13(LDO_OUT) U15.16(DCDC_IN)
NetC52_1: C52.1 U14.13(LDO_OUT) U14.16(DCDC_IN)
NetR64_1: R64.1 R253.2
NetR64_2: R64.2 R252.1
NetR65_1: R65.1 R252.2
NetR65_2: R65.2 R251.1
NetR66_1: R66.1 R251.2
NetR67_1: R67.1 U14.10(OUTN)
NetR69_1: R69.1 U15.14(DIAG)
NetR70_1: R70.1 U14.11(OUTP)
NetR72_1: R72.1 R267.2 R274.1
NetR76_1: R76.1 R253.1 R260.2
NetR78_1: R78.1 U15.11(OUTP)
NetR80_1: R80.1 U14.14(DIAG)
NetR82_1: R82.1 U15.10(OUTN)
NetR84_1: R84.1 R276.2
NetR85_1: R85.1 R275.2
NetR85_2: R85.2 R276.1
NetR86_1: R86.1 R274.2
NetR86_2: R86.2 R275.1
NetR95_1: R95.1 R298.2 U20.3(-IN)
NetR98_1: R98.1 R101.2 U20.1(+IN)
NetR100_1: R100.1 R298.1 U20.4(OUT)
NetR102_1: R102.1 R308.2 U21.3(-IN)
NetR107_1: R107.1 R308.1 U21.4(OUT)
NetR108_1: R108.1 R112.2 U21.1(+IN)

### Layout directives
net class S-_CLASS: DCDCO_S, GND_S, HLDOO_N, INP_S, NCS_NOTUSED, S-
net class P-_CLASS: DCDCO_P, GND_P, HLDOO_P, INP_P, NCP_NOTUSED, P-
net class PMID_CLASS: DCDCO_P, GND_P, HLDOO_P, INP_P, NCP_NOTUSED, P-
net class SMID_CLASS: DCDCO_S, GND_S, HLDOO_N, INP_S, NCS_NOTUSED, S-
net class P+_CLASS: P+
net class S+_CLASS: S+

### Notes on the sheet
- (near R308) PRIMARY DC VOLTAGE DIFFERENTIAL TO SINGLE-ENDED - NON-ISOLATED
- (near R298) PRIMARY DC VOLTAGE DIFFERENTIAL TO SINGLE-ENDED - NON-ISOLATED

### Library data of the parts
C38 C45 C48 C53 C172 C175 = GCM188R71H102KA37D: CAP CER 1000PF 50V X7R 0603; Manufacturer: MURATA; Tolerance: 10%
C39 C41 C50 C52 C64 C67 C174 C177 = CGA3E2X7R1H104K080AA: CAP CER 0.1UF 50V X7R 0603; Manufacturer: TDK; Material: 4241ConductorMaterial; Tolerance: 10%
C40 C46 C47 C51 = GRM188R72A103KA01D: CAP CER 10000PF 100V X7R 0603; Manufacturer: MURATA; Material: Ceramic; Tolerance: 10%
C43 C49 C170 C182 = CGA3E1X7R1V105K080AC: as C189 on sheet Level Shifting
C201 C209 = GCM1885C2A221JA16D: CAP CER 220PF 100V C0G/NP0 0603; Manufacturer: MURATA; Material: 4241ConductorMaterial; Tolerance: 5%; Dielectric: C0G; Dissipation Factor: 0.01%; Temperature Coefficient: 30ppm/°C
R64-R66 R84-R86 R251-R253 R274-R276 = RNCF1206BKE1M00: RES SMD 1M OHM 0.1% 1/3W 1206; Manufacturer: STACKPOLE; Description: Fixed Resistor, Thin Film, 0.33W, 1000000ohm, 200V, 0.1% +/-Tol, 25ppm/Cel, Surface Mount, 1206; Additional Feature: PRECISION; Power: 0.33W; Rated Temperature: 70°C; Working Voltage: 200V; Temperature Coefficient (ppm/Cel): 25; Package Height: 0.55mm; Package Length: 3.05mm; Package Width: 1.55mm; Reference Standard: AEC-Q200
R67 R70-R72 R76-R78 R82 = CRCW06030000Z0EB: RES SMD 0 OHM JUMPER 1/10W 0603; Manufacturer: VISHAY DALE; Max Power Dissipation: 100mW; Voltage Rating: 75V; Tolerance: 1%; Temperature Coefficient: 100ppm/°C; Value: 0Ω
R69 R80 R95 R98 R102 R108 = ERJ3EKF1002V: as R295 on sheet Fault Logic - S
R100 R107 = RC0603JR-1310RL: RES 10 OHM 5% 1/10W 0603; Manufacturer: YAGEO
R101 R112 R298 R308 = RT0603DRD0716K5L: RES SMD 16.5KOHM 0.5% 1/10W 0603; Manufacturer: YAGEO; Voltage Rating: 75V; Temperature Coefficient: 25 ppm/°C; Tolerance: 0.005
R260 R267 = ERA-3AEB5621V: RES SMD 5.62KOHM 0.1% 1/10W 0603; Manufacturer: PANASONIC; Description: Fixed Resistor, Thin Film, 0.1W, 5620ohm, 75V, 0.1% +/-Tol, 25ppm/Cel, Surface Mount, 0603; Power: 0.1W; Rated Temperature: 85°C; Working Voltage: 75V; Temperature Coefficient (ppm/Cel): 25; Package Height: 0.45mm; Package Length: 1.6mm; Package Width: 0.8mm; Reference Standard: AEC-Q200
U14 U15 = AMC3330QDWERQ1: IC ISOLATED AMPLIFIER
U20 U21 = CMP-04895-000486-1: IC OPAMP GP 1 CIRCUIT SC70-5; Gain Bandwidth Product: 1MHz; Operating Supply Current: 75uA; Input Bias Current: 1pA; Output Current per Channel: 15mA; Input Offset Voltage (Vos): 750uV; Number of Circuits: 1; Slew Rate: 0.5V/µs

## Sheet Current Sense - P.SchDoc: CURRENT SENSE (P) - 60KW GM4 DAB CONTROL
size 431 x 279 mm; Date: 02/2025; DocumentNumber: CRD60DD12N-GMB-CONTROL; Revision: 2.0; SheetNumber: 11; SheetTotal: 12; SheetSize: B
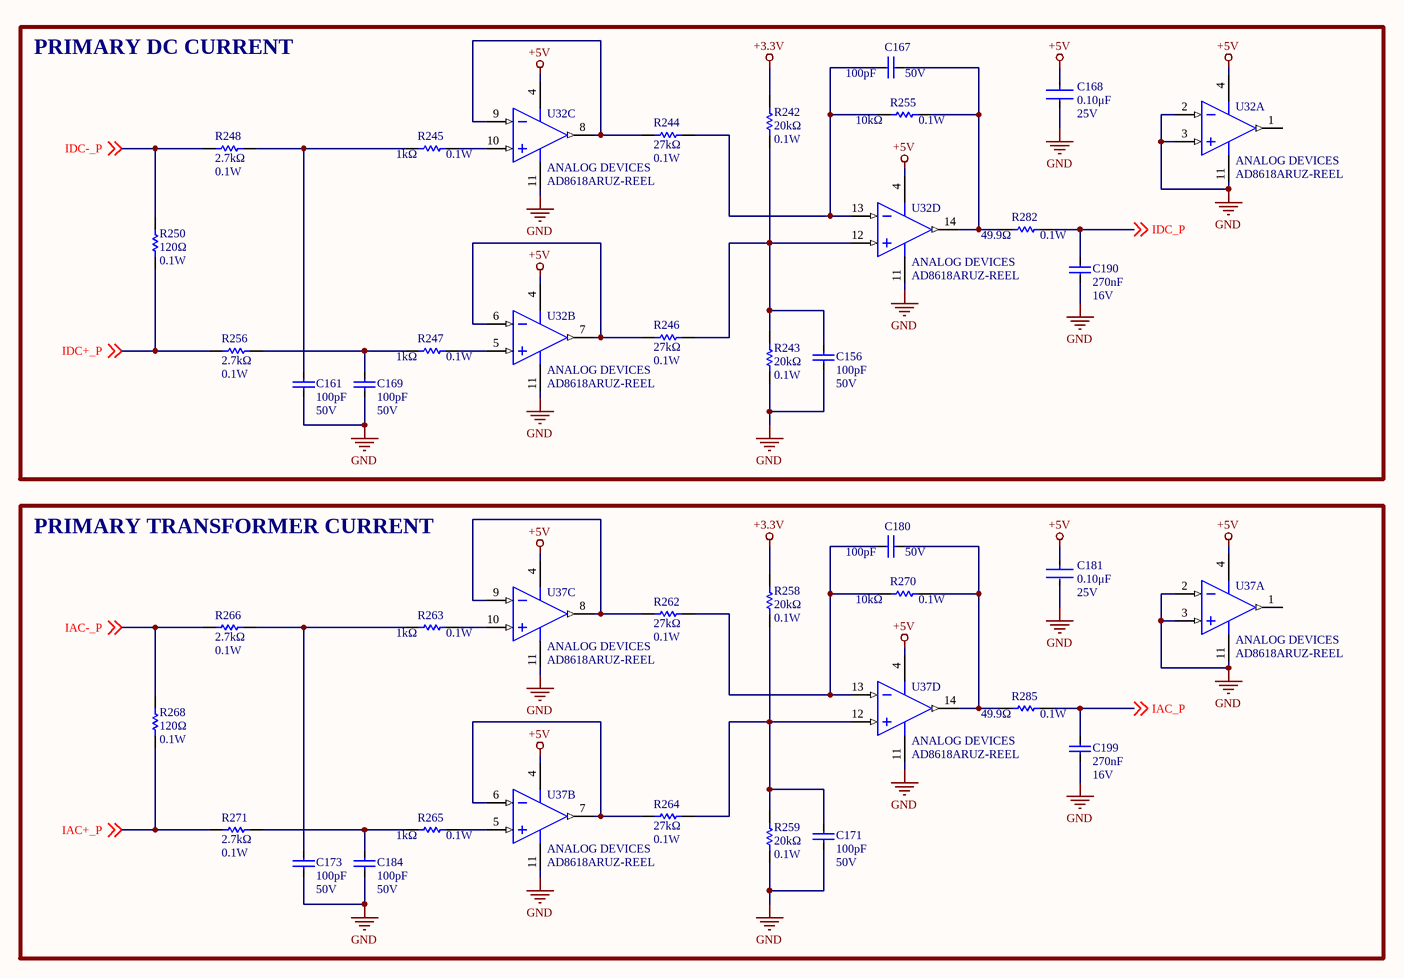
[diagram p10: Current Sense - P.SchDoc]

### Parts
C156  Capacitance: 100pF  Voltage: 50V  [FP-C0603C-CF-IPC_B]  (hidden comment: CL10C101JB8NNNC)
C161  Capacitance: 100pF  Voltage: 50V  [FP-C0603C-CF-IPC_B]  (hidden comment: CL10C101JB8NNNC)
C167  Capacitance: 100pF  Voltage: 50V  [FP-C0603C-CF-IPC_B]  (hidden comment: CL10C101JB8NNNC)
C168  Voltage Rating: 25V  Capacitance: 0.10μF  [FP-C0603C-CF-IPC_B]  (hidden comment: C0603C104K3RACTU)
C169  Capacitance: 100pF  Voltage: 50V  [FP-C0603C-CF-IPC_B]  (hidden comment: CL10C101JB8NNNC)
C171  Capacitance: 100pF  Voltage: 50V  [FP-C0603C-CF-IPC_B]  (hidden comment: CL10C101JB8NNNC)
C173  Capacitance: 100pF  Voltage: 50V  [FP-C0603C-CF-IPC_B]  (hidden comment: CL10C101JB8NNNC)
C180  Capacitance: 100pF  Voltage: 50V  [FP-C0603C-CF-IPC_B]  (hidden comment: CL10C101JB8NNNC)
C181  Voltage Rating: 25V  Capacitance: 0.10μF  [FP-C0603C-CF-IPC_B]  (hidden comment: C0603C104K3RACTU)
C184  Capacitance: 100pF  Voltage: 50V  [FP-C0603C-CF-IPC_B]  (hidden comment: CL10C101JB8NNNC)
C190  value 270nF  Voltage: 16V  [FP-C0603C-CF-IPC_B]  (hidden comment: GCM188R71C274KA37D)
C199  value 270nF  Voltage: 16V  [FP-C0603C-CF-IPC_B]  (hidden comment: GCM188R71C274KA37D)
R242  Resistance: 20kΩ  Power Rating: 0.1W  [FP-MCR03-IPC_B]  (hidden comment: CRCW060320K0FKTA)
R243  Resistance: 20kΩ  Power Rating: 0.1W  [FP-MCR03-IPC_B]  (hidden comment: CRCW060320K0FKTA)
R244  value 27kΩ  Power Rating: 0.1W  [FP-MCR03-IPC_B]  (hidden comment: RC0603FR-0727KL)
R245  value 1kΩ  Power: 0.1W  [FP-MCR03-IPC_B]  (hidden comment: RC0603JR-101KL)
R246  value 27kΩ  Power Rating: 0.1W  [FP-MCR03-IPC_B]  (hidden comment: RC0603FR-0727KL)
R247  value 1kΩ  Power: 0.1W  [FP-MCR03-IPC_B]  (hidden comment: RC0603JR-101KL)
R248  value 2.7kΩ  Power Rating: 0.1W  [FP-MCR03-IPC_B]  (hidden comment: RT0603BRD072K7L)
R250  value 120Ω  Max Power Dissipation: 0.1W  [FP-MCR03-IPC_B]  (hidden comment: RC0603JR-07120RL)
R255  value 10kΩ  Max Power Dissipation: 0.1W  [FP-MCR03-IPC_B]  (hidden comment: ERJ3EKF1002V)
R256  value 2.7kΩ  Power Rating: 0.1W  [FP-MCR03-IPC_B]  (hidden comment: RT0603BRD072K7L)
R258  Resistance: 20kΩ  Power Rating: 0.1W  [FP-MCR03-IPC_B]  (hidden comment: CRCW060320K0FKTA)
R259  Resistance: 20kΩ  Power Rating: 0.1W  [FP-MCR03-IPC_B]  (hidden comment: CRCW060320K0FKTA)
R262  value 27kΩ  Power Rating: 0.1W  [FP-MCR03-IPC_B]  (hidden comment: RC0603FR-0727KL)
R263  value 1kΩ  Power: 0.1W  [FP-MCR03-IPC_B]  (hidden comment: RC0603JR-101KL)
R264  value 27kΩ  Power Rating: 0.1W  [FP-MCR03-IPC_B]  (hidden comment: RC0603FR-0727KL)
R265  value 1kΩ  Power: 0.1W  [FP-MCR03-IPC_B]  (hidden comment: RC0603JR-101KL)
R266  value 2.7kΩ  Power Rating: 0.1W  [FP-MCR03-IPC_B]  (hidden comment: RT0603BRD072K7L)
R268  value 120Ω  Max Power Dissipation: 0.1W  [FP-MCR03-IPC_B]  (hidden comment: RC0603JR-07120RL)
R270  value 10kΩ  Max Power Dissipation: 0.1W  [FP-MCR03-IPC_B]  (hidden comment: ERJ3EKF1002V)
R271  value 2.7kΩ  Power Rating: 0.1W  [FP-MCR03-IPC_B]  (hidden comment: RT0603BRD072K7L)
R282  Resistance: 49.9Ω  Power Rating: 0.1W  [FP-MCR03-IPC_B]  (hidden comment: ERJ-3EKF49R9V)
R285  Resistance: 49.9Ω  Power Rating: 0.1W  [FP-MCR03-IPC_B]  (hidden comment: ERJ-3EKF49R9V)
U32  AD8618ARUZ-REEL  Manufacturer: ANALOG DEVICES  [ADI-RU-14_L]  (parts A,B,C,D of 4)
U37  AD8618ARUZ-REEL  Manufacturer: ANALOG DEVICES  [ADI-RU-14_L]  (parts A,B,C,D of 4)

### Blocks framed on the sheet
PRIMARY DC CURRENT: C156 C161 C167-C169 C190 R242-R248 R250 R255 R256 R282 U32
PRIMARY TRANSFORMER CURRENT: C171 C173 C180 C181 C184 C199 R258 R259 R262-R266 R268 R270 R271 R285 U37

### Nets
+3.3V: R242.2 R258.2
+5V: C168.1 C181.1 U32.4(+V) U37.4(+V)
GND: C156.2 C161.2 C168.2 C169.2 C171.2 C173.2 C181.2 C184.2 C190.2 C199.2 R243.1 R259.1 U32.2(-IN_A) U32.3(+IN_A) U32.11(-V) U37.2(-IN_A) U37.3(+IN_A) U37.11(-V)
IAC+_P: R268.1 R271.1 ; off-sheet IAC+_P
IAC-_P: R266.1 R268.2 ; off-sheet IAC-_P
IAC_P: C199.1 R285.2 ; off-sheet IAC_P
IDC+_P: R250.1 R256.1 ; off-sheet IDC+_P
IDC-_P: R248.1 R250.2 ; off-sheet IDC-_P
IDC_P: C190.1 R282.2 ; off-sheet IDC_P
NetC156_1: C156.1 R242.1 R243.2 R246.2 U32.12(+IN_D)
NetC161_1: C161.1 R245.1 R248.2
NetC167_1: C167.1 R244.2 R255.2 U32.13(-IN_D)
NetC167_2: C167.2 R255.1 R282.1 U32.14(OUT_D)
NetC169_1: C169.1 R247.1 R256.2
NetC171_1: C171.1 R258.1 R259.2 R264.2 U37.12(+IN_D)
NetC173_1: C173.1 R263.1 R266.2
NetC180_1: C180.1 R262.2 R270.2 U37.13(-IN_D)
NetC180_2: C180.2 R270.1 R285.1 U37.14(OUT_D)
NetC184_1: C184.1 R265.1 R271.2
NetR244_1: R244.1 U32.8(OUT_C) U32.9(-IN_C)
NetR245_2: R245.2 U32.10(+IN_C)
NetR246_1: R246.1 U32.6(-IN_B) U32.7(OUT_B)
NetR247_2: R247.2 U32.5(+IN_B)
NetR262_1: R262.1 U37.8(OUT_C) U37.9(-IN_C)
NetR263_2: R263.2 U37.10(+IN_C)
NetR264_1: R264.1 U37.6(-IN_B) U37.7(OUT_B)
NetR265_2: R265.2 U37.5(+IN_B)

Not connected (* = marked no-connect by the designer): U32 1(OUT_A); U37 1(OUT_A)

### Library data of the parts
C156 C161 C167 C169 C171 C173 C180 C184 = CL10C101JB8NNNC: CAP CER 100PF 50V C0G/NP0 0603; Manufacturer: SAMSUNG; Material: Ceramic; Tolerance: 5%; Dielectric: C0G; Temperature Coefficient: 300ppm/°C
C168 C181 = CMP-2006-03057-2: CAP CER 0.1UF 25V X7R 0603; Manufacturer: KEMET; Value: 0.10μF; Material: Ceramic; Tolerance: 0.1; Temperature Coefficient: 30ppm/°C; Automotive Grade: Grade 1
C190 C199 = GCM188R71C274KA37D: CAP CER 0.27UF 16V X7R 0603; Manufacturer: MURATA; Tolerance: 10%
R242 R243 R258 R259 = CRCW060320K0FKTA: RES SMD 20K OHM 1% 1/10W 0603; Manufacturer: VISHAY DALE; Temperature Coefficient: 100ppm/°C; Voltage Rating: 75V; Max Power Dissipation: 100mW; Value: 20kΩ
R244 R246 R262 R264 = RC0603FR-0727KL: RES 27K OHM 1% 1/10W 0603; Manufacturer: YAGEO; Temperature Coefficient: 100PPM/C; Voltage Rating: 50V
R245 R247 R263 R265 = CMP-2000-04305-1: RES 1K OHM 5% 1/10W 0603; Manufacturer: YAGEO
R248 R256 R266 R271 = RT0603BRD072K7L: RES SMD 2.7K OHM 0.1% 1/10W 0603; Manufacturer: YAGEO; Temperature Coefficient: 25 ppm/°C; Tolerance: 0.001; Voltage Rating: 75V
R250 R268 = RC0603JR-07120RL: as R249 on sheet Fault Logic - S
R255 R270 = ERJ3EKF1002V: as R295 on sheet Fault Logic - S
R282 R285 = ERJ-3EKF49R9V: as R74 on sheet Level Shifting
U32 U37 = CMP-0384-01836-1: IC CMOS 4 CIRCUIT 14TSSOP; Generic Part Number: AD8618; Slew Rate: 12V/us; Amplifiers Per Package: 4; V Span Min: 2.7V; Input Offset Voltage: 23uV; V Span Max: 6V; Iq/Amp: 2mA; Small Signal Bandwidth: 24MHz; Input Bias Current: 200fA

## Sheet Current Sense - S.SchDoc: CURRENT SENSE (S) - 60KW GM4 DAB CONTROL
size 431 x 279 mm; Date: 02/2025; DocumentNumber: CRD60DD12N-GMB-CONTROL; Revision: 2.0; SheetNumber: 12; SheetTotal: 12; SheetSize: B
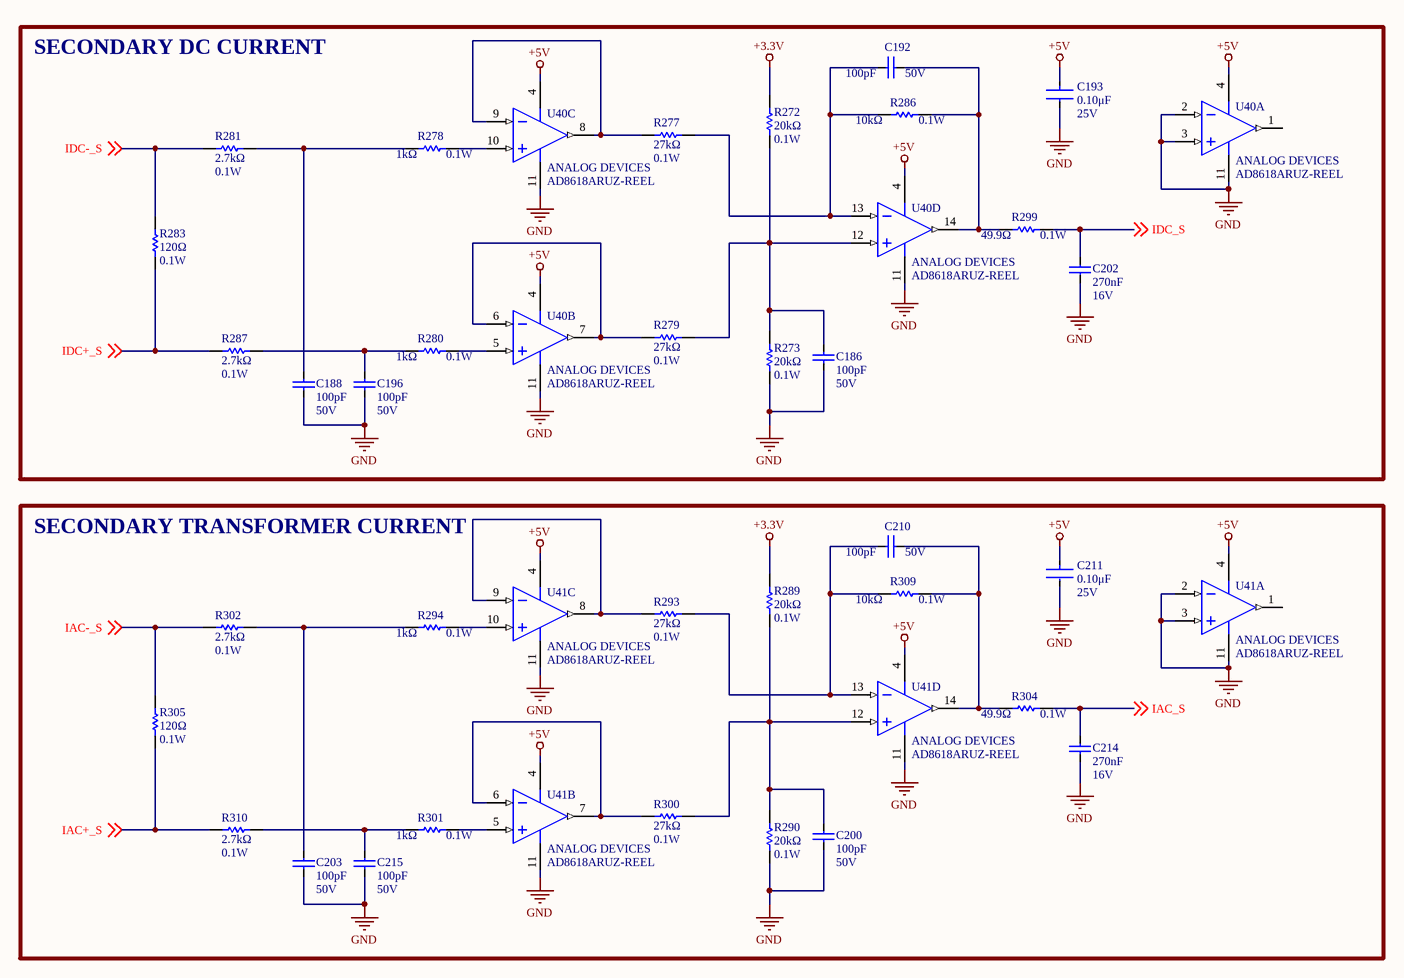
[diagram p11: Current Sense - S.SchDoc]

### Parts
C186  Capacitance: 100pF  Voltage: 50V  [FP-C0603C-CF-IPC_B]  (hidden comment: CL10C101JB8NNNC)
C188  Capacitance: 100pF  Voltage: 50V  [FP-C0603C-CF-IPC_B]  (hidden comment: CL10C101JB8NNNC)
C192  Capacitance: 100pF  Voltage: 50V  [FP-C0603C-CF-IPC_B]  (hidden comment: CL10C101JB8NNNC)
C193  Voltage Rating: 25V  Capacitance: 0.10μF  [FP-C0603C-CF-IPC_B]  (hidden comment: C0603C104K3RACTU)
C196  Capacitance: 100pF  Voltage: 50V  [FP-C0603C-CF-IPC_B]  (hidden comment: CL10C101JB8NNNC)
C200  Capacitance: 100pF  Voltage: 50V  [FP-C0603C-CF-IPC_B]  (hidden comment: CL10C101JB8NNNC)
C202  value 270nF  Voltage: 16V  [FP-C0603C-CF-IPC_B]  (hidden comment: GCM188R71C274KA37D)
C203  Capacitance: 100pF  Voltage: 50V  [FP-C0603C-CF-IPC_B]  (hidden comment: CL10C101JB8NNNC)
C210  Capacitance: 100pF  Voltage: 50V  [FP-C0603C-CF-IPC_B]  (hidden comment: CL10C101JB8NNNC)
C211  Voltage Rating: 25V  Capacitance: 0.10μF  [FP-C0603C-CF-IPC_B]  (hidden comment: C0603C104K3RACTU)
C214  value 270nF  Voltage: 16V  [FP-C0603C-CF-IPC_B]  (hidden comment: GCM188R71C274KA37D)
C215  Capacitance: 100pF  Voltage: 50V  [FP-C0603C-CF-IPC_B]  (hidden comment: CL10C101JB8NNNC)
R272  Resistance: 20kΩ  Power Rating: 0.1W  [FP-MCR03-IPC_B]  (hidden comment: CRCW060320K0FKTA)
R273  Resistance: 20kΩ  Power Rating: 0.1W  [FP-MCR03-IPC_B]  (hidden comment: CRCW060320K0FKTA)
R277  value 27kΩ  Power Rating: 0.1W  [FP-MCR03-IPC_B]  (hidden comment: RC0603FR-0727KL)
R278  value 1kΩ  Power: 0.1W  [FP-MCR03-IPC_B]  (hidden comment: RC0603JR-101KL)
R279  value 27kΩ  Power Rating: 0.1W  [FP-MCR03-IPC_B]  (hidden comment: RC0603FR-0727KL)
R280  value 1kΩ  Power: 0.1W  [FP-MCR03-IPC_B]  (hidden comment: RC0603JR-101KL)
R281  value 2.7kΩ  Power Rating: 0.1W  [FP-MCR03-IPC_B]  (hidden comment: RT0603BRD072K7L)
R283  value 120Ω  Max Power Dissipation: 0.1W  [FP-MCR03-IPC_B]  (hidden comment: RC0603JR-07120RL)
R286  value 10kΩ  Max Power Dissipation: 0.1W  [FP-MCR03-IPC_B]  (hidden comment: ERJ3EKF1002V)
R287  value 2.7kΩ  Power Rating: 0.1W  [FP-MCR03-IPC_B]  (hidden comment: RT0603BRD072K7L)
R289  Resistance: 20kΩ  Power Rating: 0.1W  [FP-MCR03-IPC_B]  (hidden comment: CRCW060320K0FKTA)
R290  Resistance: 20kΩ  Power Rating: 0.1W  [FP-MCR03-IPC_B]  (hidden comment: CRCW060320K0FKTA)
R293  value 27kΩ  Power Rating: 0.1W  [FP-MCR03-IPC_B]  (hidden comment: RC0603FR-0727KL)
R294  value 1kΩ  Power: 0.1W  [FP-MCR03-IPC_B]  (hidden comment: RC0603JR-101KL)
R299  Resistance: 49.9Ω  Power Rating: 0.1W  [FP-MCR03-IPC_B]  (hidden comment: ERJ-3EKF49R9V)
R300  value 27kΩ  Power Rating: 0.1W  [FP-MCR03-IPC_B]  (hidden comment: RC0603FR-0727KL)
R301  value 1kΩ  Power: 0.1W  [FP-MCR03-IPC_B]  (hidden comment: RC0603JR-101KL)
R302  value 2.7kΩ  Power Rating: 0.1W  [FP-MCR03-IPC_B]  (hidden comment: RT0603BRD072K7L)
R304  Resistance: 49.9Ω  Power Rating: 0.1W  [FP-MCR03-IPC_B]  (hidden comment: ERJ-3EKF49R9V)
R305  value 120Ω  Max Power Dissipation: 0.1W  [FP-MCR03-IPC_B]  (hidden comment: RC0603JR-07120RL)
R309  value 10kΩ  Max Power Dissipation: 0.1W  [FP-MCR03-IPC_B]  (hidden comment: ERJ3EKF1002V)
R310  value 2.7kΩ  Power Rating: 0.1W  [FP-MCR03-IPC_B]  (hidden comment: RT0603BRD072K7L)
U40  AD8618ARUZ-REEL  Manufacturer: ANALOG DEVICES  [ADI-RU-14_L]  (parts A,B,C,D of 4)
U41  AD8618ARUZ-REEL  Manufacturer: ANALOG DEVICES  [ADI-RU-14_L]  (parts A,B,C,D of 4)

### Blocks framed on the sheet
SECONDARY DC CURRENT: C186 C188 C192 C193 C196 C202 R272 R273 R277-R281 R283 R286 R287 R299 U40
SECONDARY TRANSFORMER CURRENT: C200 C203 C210 C211 C214 C215 R289 R290 R293 R294 R300-R302 R304 R305 R309 R310 U41

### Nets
+3.3V: R272.2 R289.2
+5V: C193.1 C211.1 U40.4(+V) U41.4(+V)
GND: C186.2 C188.2 C193.2 C196.2 C200.2 C202.2 C203.2 C211.2 C214.2 C215.2 R273.1 R290.1 U40.2(-IN_A) U40.3(+IN_A) U40.11(-V) U41.2(-IN_A) U41.3(+IN_A) U41.11(-V)
IAC+_S: R305.1 R310.1 ; off-sheet IAC+_S
IAC-_S: R302.1 R305.2 ; off-sheet IAC-_S
IAC_S: C214.1 R304.2 ; off-sheet IAC_S
IDC+_S: R283.1 R287.1 ; off-sheet IDC+_S
IDC-_S: R281.1 R283.2 ; off-sheet IDC-_S
IDC_S: C202.1 R299.2 ; off-sheet IDC_S
NetC186_1: C186.1 R272.1 R273.2 R279.2 U40.12(+IN_D)
NetC188_1: C188.1 R278.1 R281.2
NetC192_1: C192.1 R277.2 R286.2 U40.13(-IN_D)
NetC192_2: C192.2 R286.1 R299.1 U40.14(OUT_D)
NetC196_1: C196.1 R280.1 R287.2
NetC200_1: C200.1 R289.1 R290.2 R300.2 U41.12(+IN_D)
NetC203_1: C203.1 R294.1 R302.2
NetC210_1: C210.1 R293.2 R309.2 U41.13(-IN_D)
NetC210_2: C210.2 R304.1 R309.1 U41.14(OUT_D)
NetC215_1: C215.1 R301.1 R310.2
NetR277_1: R277.1 U40.8(OUT_C) U40.9(-IN_C)
NetR278_2: R278.2 U40.10(+IN_C)
NetR279_1: R279.1 U40.6(-IN_B) U40.7(OUT_B)
NetR280_2: R280.2 U40.5(+IN_B)
NetR293_1: R293.1 U41.8(OUT_C) U41.9(-IN_C)
NetR294_2: R294.2 U41.10(+IN_C)
NetR300_1: R300.1 U41.6(-IN_B) U41.7(OUT_B)
NetR301_2: R301.2 U41.5(+IN_B)

Not connected (* = marked no-connect by the designer): U40 1(OUT_A); U41 1(OUT_A)

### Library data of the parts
C186 C188 C192 C196 C200 C203 C210 C215 = CL10C101JB8NNNC: as C156 on sheet Current Sense - P
C193 C211 = CMP-2006-03057-2: as C168 on sheet Current Sense - P
C202 C214 = GCM188R71C274KA37D: as C190 on sheet Current Sense - P
R272 R273 R289 R290 = CRCW060320K0FKTA: as R242 on sheet Current Sense - P
R277 R279 R293 R300 = RC0603FR-0727KL: as R244 on sheet Current Sense - P
R278 R280 R294 R301 = CMP-2000-04305-1: as R245 on sheet Current Sense - P
R281 R287 R302 R310 = RT0603BRD072K7L: as R248 on sheet Current Sense - P
R283 R305 = RC0603JR-07120RL: as R249 on sheet Fault Logic - S
R286 R309 = ERJ3EKF1002V: as R295 on sheet Fault Logic - S
R299 R304 = ERJ-3EKF49R9V: as R74 on sheet Level Shifting
U40 U41 = CMP-0384-01836-1: as U32 on sheet Current Sense - P

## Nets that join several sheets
+3.3V: Controller (15 pins), Input-Output (5 pins), Level Shifting (11 pins), Voltage Sense (C64.1 C67.1 U20.5 U21.5), Current Sense - P (R242.2 R258.2), Current Sense - S (R272.2 R289.2)
+5V: Controller (12 pins), Input-Output (7 pins), Drivers - 12P (6 pins), Drivers - 34P (6 pins), Drivers - 12S (6 pins), Drivers - 34S (6 pins), Fault Logic - P (28 pins), Fault Logic - S (28 pins), Level Shifting (10 pins), Voltage Sense (8 pins), Current Sense - P (C168.1 C181.1 U32.4 U37.4), Current Sense - S (C193.1 C211.1 U40.4 U41.4)
+12V: Controller (14 pins), Input-Output (J1.1 J13.1 TP1.1), Drivers - 12P (10 pins), Drivers - 34P (10 pins), Drivers - 12S (10 pins), Drivers - 34S (10 pins)
GND: Controller (59 pins), Input-Output (24 pins), Drivers - 12P (44 pins), Drivers - 34P (44 pins), Drivers - 12S (44 pins), Drivers - 34S (44 pins), Fault Logic - P (36 pins), Fault Logic - S (36 pins), Level Shifting (37 pins), Voltage Sense (18 pins), Current Sense - P (18 pins), Current Sense - S (18 pins)
VIN: Controller (Q1.5 R7.2 R8.2 U1.1), Input-Output (J11.1)
APWM_P: Drivers - 12P (U10.16), Level Shifting (U35.2)
APWM_S: Drivers - 12S (U24.16), Level Shifting (U35.3)
CAN_RX: Controller (U9.87), Input-Output (U2.4)
CAN_TX: Controller (U9.88), Input-Output (U2.1)
D_1S: Input-Output (J14.084), Drivers - 12S (D26.1)
D_2P: Input-Output (J14.035), Drivers - 12P (D10.1)
D_2S: Input-Output (J14.091), Drivers - 12S (D25.1)
D_3S: Input-Output (J14.083), Drivers - 34S (D23.1)
D_4P: Input-Output (J14.019), Drivers - 34P (D9.1)
D_4S: Input-Output (J14.076), Drivers - 34S (D24.1)
D_13P: Input-Output (J14.027), Drivers - 12P (D11.1), Drivers - 34P (D8.1)
~{ERR_1P}: Fault Logic - P (C163.1 R73.1), Level Shifting (U13.2)
~{ERR_1P_BUF}: Controller (U9.77), Level Shifting (U13.13)
~{ERR_1S}: Fault Logic - S (C160.1 R249.1), Level Shifting (U36.2)
~{ERR_1S_BUF}: Controller (U9.78), Level Shifting (U36.13)
~{ERR_2P}: Fault Logic - P (C159.1 R68.1), Level Shifting (U13.3)
~{ERR_2P_BUF}: Controller (U9.79), Level Shifting (U13.12)
~{ERR_2S}: Fault Logic - S (C179.1 R254.1), Level Shifting (U36.3)
~{ERR_2S_BUF}: Controller (U9.80), Level Shifting (U36.12)
~{ERR_3P}: Fault Logic - P (C154.1 R63.1), Level Shifting (U13.4)
~{ERR_3P_BUF}: Controller (U9.81), Level Shifting (U13.11)
~{ERR_3S}: Fault Logic - S (C183.1 R257.1), Level Shifting (U36.4)
~{ERR_3S_BUF}: Controller (U9.91), Level Shifting (U36.11)
~{ERR_4P}: Fault Logic - P (C151.1 R62.1), Level Shifting (U13.5)
~{ERR_4P_BUF}: Controller (U9.76), Level Shifting (U13.10)
~{ERR_4S}: Fault Logic - S (C185.1 R261.1), Level Shifting (U36.5)
~{ERR_4S_BUF}: Controller (U9.92), Level Shifting (U36.10)
~{FLT_1P}: Drivers - 12P (U11.13), Fault Logic - P (R199.2 R206.1)
~{FLT_1S}: Drivers - 12S (U25.13), Fault Logic - S (R345.2 R356.1)
~{FLT_2P}: Drivers - 12P (U10.13), Fault Logic - P (R200.2 R202.1)
~{FLT_2S}: Drivers - 12S (U24.13), Fault Logic - S (R346.2 R350.1)
~{FLT_3P}: Drivers - 34P (U3.13), Fault Logic - P (R189.1 R196.2)
~{FLT_3S}: Drivers - 34S (U18.13), Fault Logic - S (R328.1 R340.2)
~{FLT_4P}: Drivers - 34P (U4.13), Fault Logic - P (R193.1 R195.2)
~{FLT_4S}: Drivers - 34S (U19.13), Fault Logic - S (R336.1 R339.2)
G1P_PWM: Controller (U9.49), Level Shifting (U16.5)
G1P_PWM_BUF: Drivers - 12P (R46.1 R57.1), Level Shifting (R83.2 U16.15)
G1S_PWM: Controller (U9.50), Level Shifting (U16.9)
G1S_PWM_BUF: Drivers - 12S (R148.1 R155.1), Level Shifting (R92.2 U16.11)
G2P_PWM: Controller (U9.51), Level Shifting (U16.4)
G2P_PWM_BUF: Drivers - 12P (R40.1 R53.1), Level Shifting (R81.2 U16.16)
G2S_PWM: Controller (U9.52), Level Shifting (U16.8)
G2S_PWM_BUF: Drivers - 12S (R144.1 R153.1), Level Shifting (R90.2 U16.12)
G3P_PWM: Controller (U9.53), Level Shifting (U16.3)
G3P_PWM_BUF: Drivers - 34P (R16.1 R23.1), Level Shifting (R79.2 U16.17)
G3S_PWM: Controller (U9.54), Level Shifting (U16.7)
G3S_PWM_BUF: Drivers - 34S (R94.1 R109.1), Level Shifting (R88.2 U16.13)
G4P_PWM: Controller (U9.55), Level Shifting (U16.2)
G4P_PWM_BUF: Drivers - 34P (R18.1 R27.1), Level Shifting (R75.2 U16.18)
G4S_PWM: Controller (U9.56), Level Shifting (U16.6)
G4S_PWM_BUF: Drivers - 34S (R99.1 R116.1), Level Shifting (R87.2 U16.14)
G_1P: Input-Output (J14.034), Drivers - 12P (5 pins)
G_1S: Input-Output (J14.092), Drivers - 12S (5 pins)
G_2P: Input-Output (J14.043), Drivers - 12P (5 pins)
G_2S: Input-Output (J14.099), Drivers - 12S (5 pins)
G_3P: Input-Output (J14.020), Drivers - 34P (5 pins)
G_3S: Input-Output (J14.075), Drivers - 34S (5 pins)
G_4P: Input-Output (J14.013), Drivers - 34P (5 pins)
G_4S: Input-Output (J14.070), Drivers - 34S (5 pins)
GD_DIS: Controller (U9.67), Level Shifting (R74.1)
IAC+_P: Input-Output (J14.004), Current Sense - P (R268.1 R271.1)
IAC+_S: Input-Output (J14.110), Current Sense - S (R305.1 R310.1)
IAC-_P: Input-Output (J14.003), Current Sense - P (R266.1 R268.2)
IAC-_S: Input-Output (J14.109), Current Sense - S (R302.1 R305.2)
IAC_P: Controller (U9.31), Current Sense - P (C199.1 R285.2)
IAC_S: Controller (U9.14), Current Sense - S (C214.1 R304.2)
IDC+_P: Input-Output (J14.002), Current Sense - P (R250.1 R256.1)
IDC+_S: Input-Output (J14.112), Current Sense - S (R283.1 R287.1)
IDC-_P: Input-Output (J14.001), Current Sense - P (R248.1 R250.2)
IDC-_S: Input-Output (J14.111), Current Sense - S (R281.1 R283.2)
IDC_P: Controller (U9.40), Current Sense - P (C190.1 R282.2)
IDC_S: Controller (U9.28), Current Sense - S (C202.1 R299.2)
NTC_P: Input-Output (J14.042), Drivers - 12P (R237.1)
NTC_S: Input-Output (J14.100), Drivers - 12S (R378.1)
P+: Input-Output (J14.049 J14.050), Voltage Sense (R66.2)
P-: Input-Output (J14.044), Voltage Sense (R71.1 R260.1)
~{PG_1P}: Drivers - 12P (U30.3), Fault Logic - P (R231.2 R235.2)
~{PG_1S}: Drivers - 12S (U44.3), Fault Logic - S (R374.2 R376.2)
~{PG_2P}: Drivers - 12P (U31.3), Fault Logic - P (R232.2 R236.2)
~{PG_2S}: Drivers - 12S (U45.3), Fault Logic - S (R375.2 R377.2)
~{PG_3P}: Drivers - 34P (U29.3), Fault Logic - P (R163.2 R165.2)
~{PG_3S}: Drivers - 34S (U43.3), Fault Logic - S (R292.2 R297.2)
~{PG_4P}: Drivers - 34P (U28.3), Fault Logic - P (R162.2 R164.2)
~{PG_4S}: Drivers - 34S (U42.3), Fault Logic - S (R291.2 R295.2)
RDY_1P: Drivers - 12P (U11.12), Fault Logic - P (R203.2 R205.1)
RDY_1S: Drivers - 12S (U25.12), Fault Logic - S (R353.2 R355.1)
RDY_2P: Drivers - 12P (U10.12), Fault Logic - P (R204.2 R207.1)
RDY_2S: Drivers - 12S (U24.12), Fault Logic - S (R354.2 R357.1)
RDY_3P: Drivers - 34P (U3.12), Fault Logic - P (R190.1 R192.2)
RDY_3S: Drivers - 34S (U18.12), Fault Logic - S (R329.1 R333.2)
RDY_4P: Drivers - 34P (U4.12), Fault Logic - P (R188.1 R191.2)
RDY_4S: Drivers - 34S (U19.12), Fault Logic - S (R327.1 R332.2)
RSTEN_P: Controller (U9.109), Level Shifting (R45.1)
RSTEN_P_BUF: Drivers - 12P (R42.1 R55.1), Drivers - 34P (R17.1 R26.1), Level Shifting (U12.18)
RSTEN_S: Controller (U9.107), Level Shifting (R52.1)
RSTEN_S_BUF: Drivers - 12S (R145.1 R154.1), Drivers - 34S (R96.1 R113.1), Level Shifting (U12.17)
S+: Input-Output (J14.061 J14.062), Voltage Sense (R84.2)
S-: Input-Output (J14.067), Voltage Sense (R77.1 R267.1)
S_1P: Input-Output (J14.033 J14.036), Drivers - 12P (10 pins)
S_1S: Input-Output (J14.089 J14.090), Drivers - 12S (10 pins)
S_2P: Input-Output (J14.041), Drivers - 12P (12 pins)
S_2S: Input-Output (J14.097), Drivers - 12S (12 pins)
S_3P: Input-Output (J14.021 J14.022), Drivers - 34P (10 pins)
S_3S: Input-Output (J14.077 J14.078), Drivers - 34S (10 pins)
S_4P: Input-Output (J14.014), Drivers - 34P (10 pins)
S_4S: Input-Output (J14.068 J14.069), Drivers - 34S (10 pins)
T_AMB: Controller (U9.21), Input-Output (R97.1 U17.1)
TEMP_P: Controller (U9.39), Level Shifting (C189.1 R89.1)
TEMP_S: Controller (U9.17), Level Shifting (C191.1 R91.1)
VDC_P: Controller (U9.11), Voltage Sense (C201.1 R100.2)
VDC_S: Controller (U9.9), Voltage Sense (C209.1 R107.2)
